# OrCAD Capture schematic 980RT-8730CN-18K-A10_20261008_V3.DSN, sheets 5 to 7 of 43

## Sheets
5 P0011_S1_DUT1: size Custom
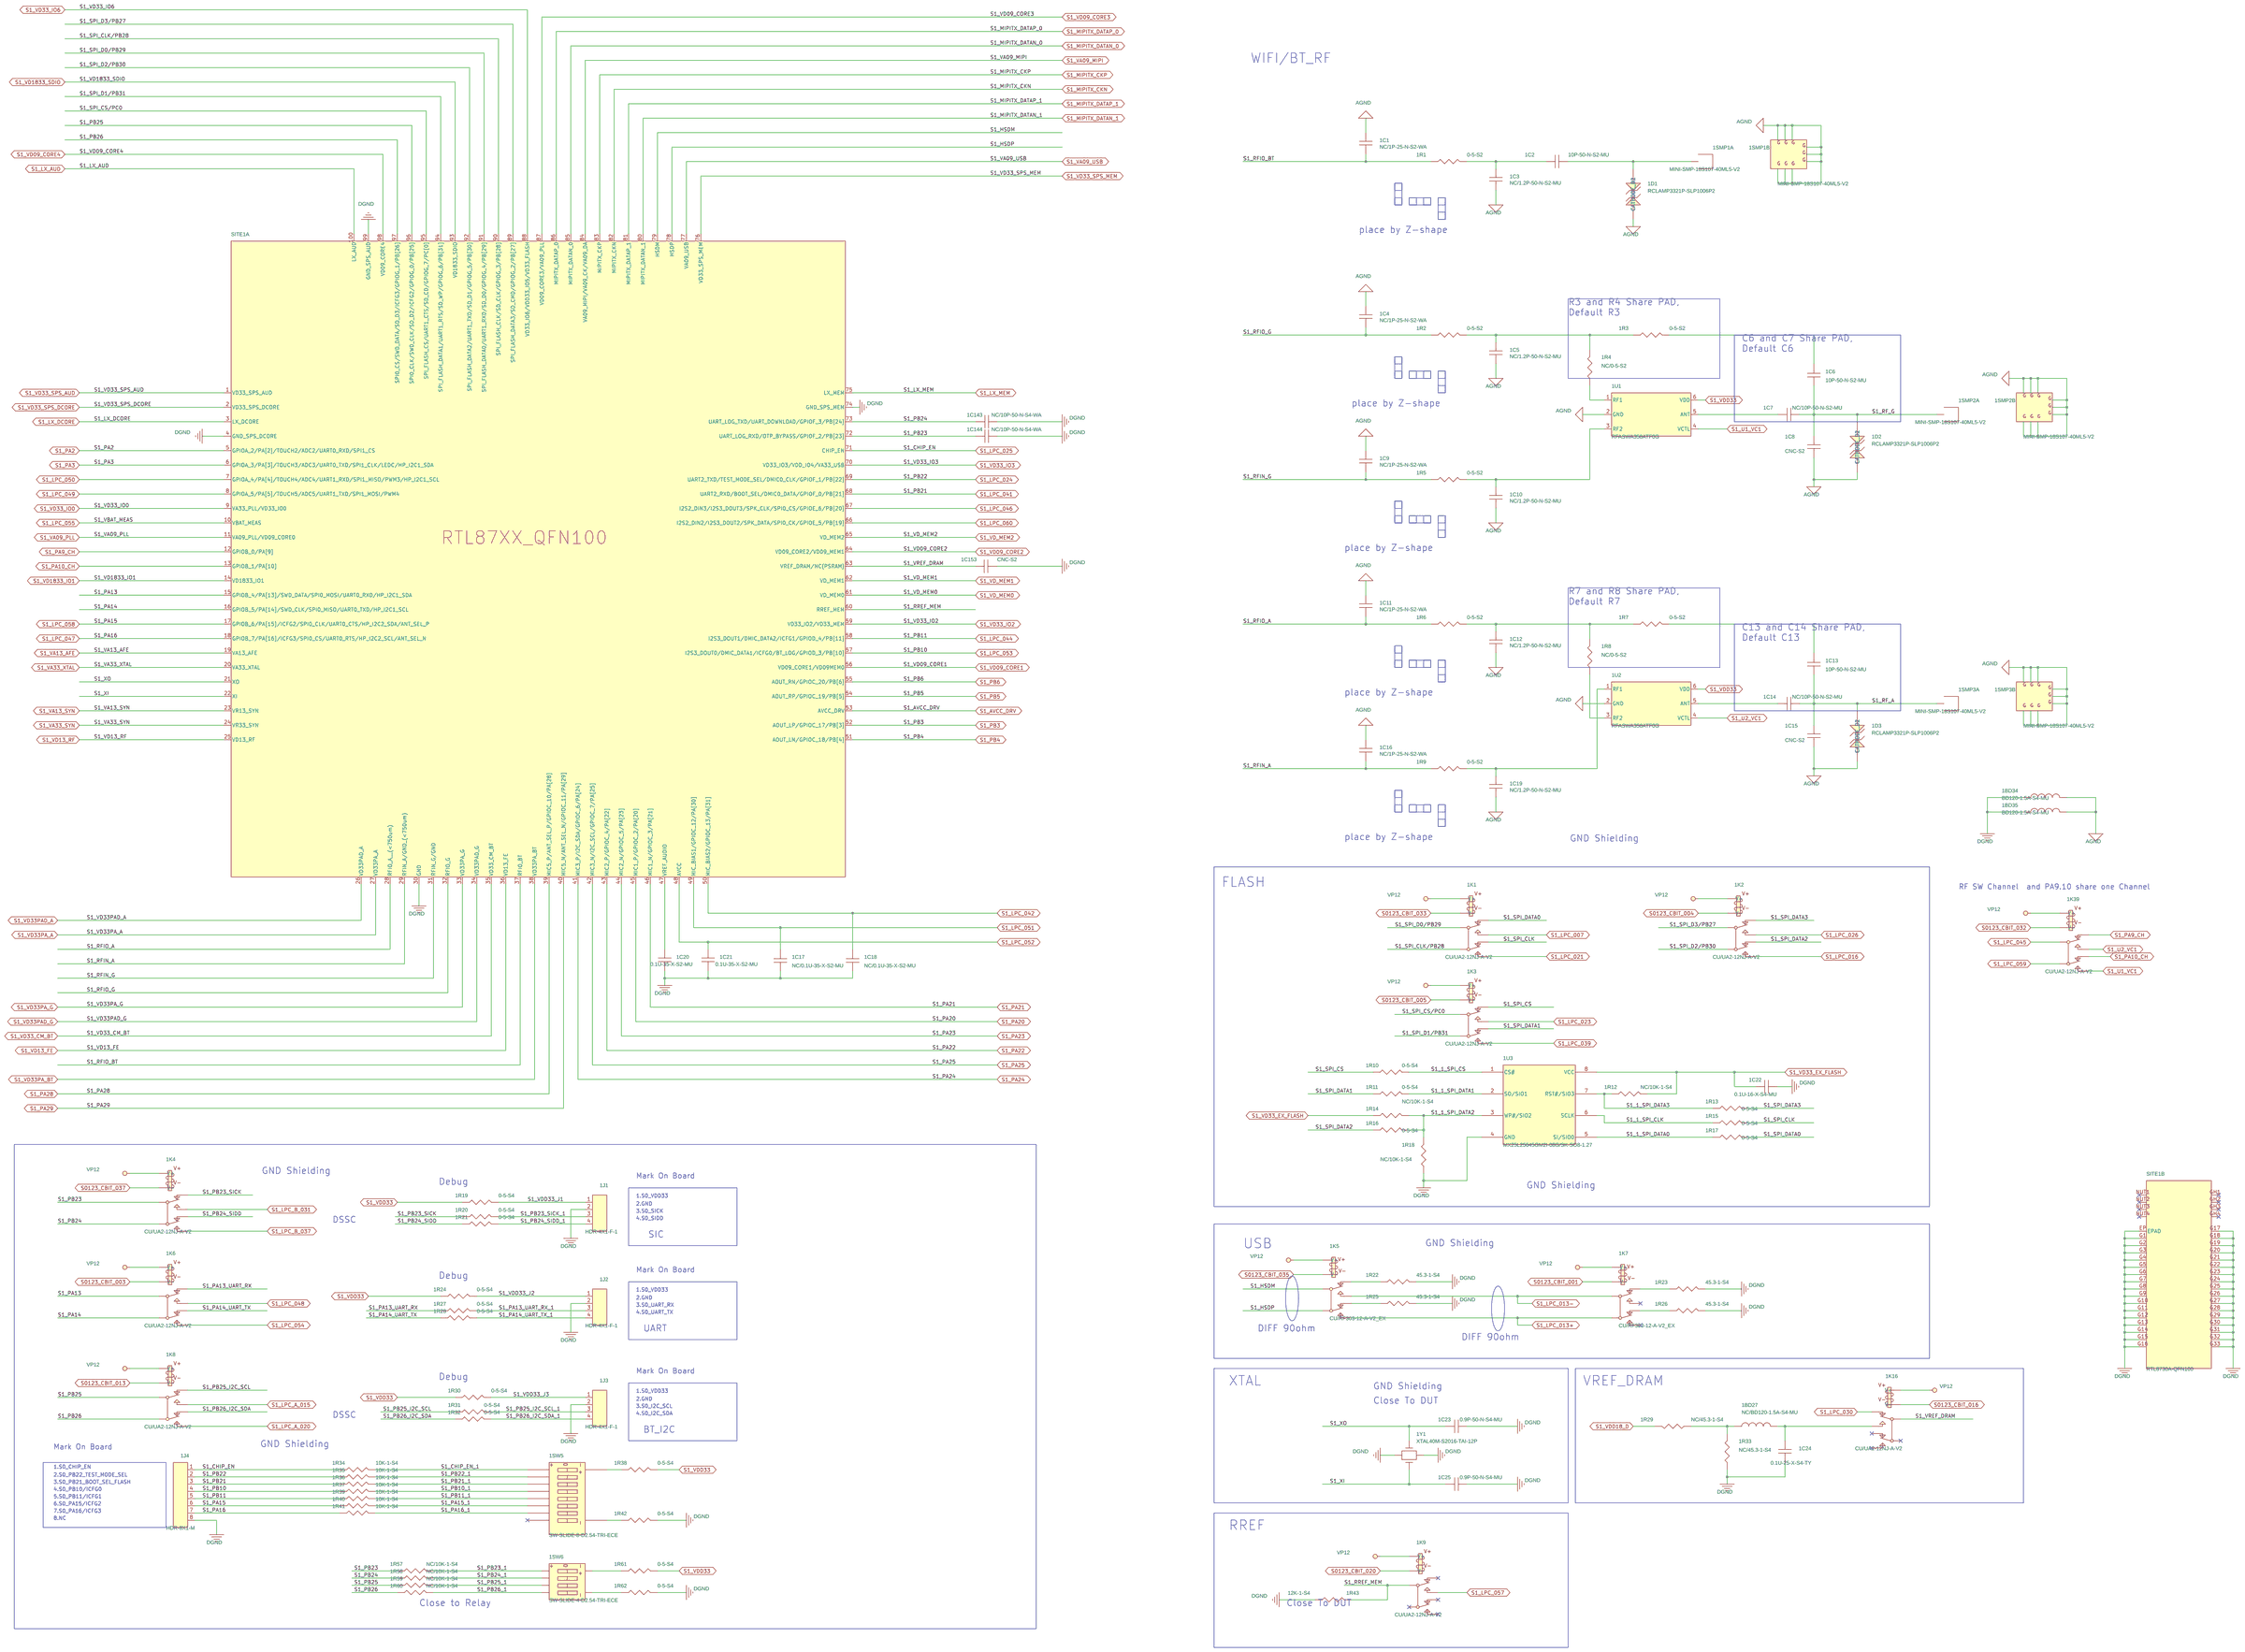
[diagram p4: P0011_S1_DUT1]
6 P0012_S1_Function-test: size A3
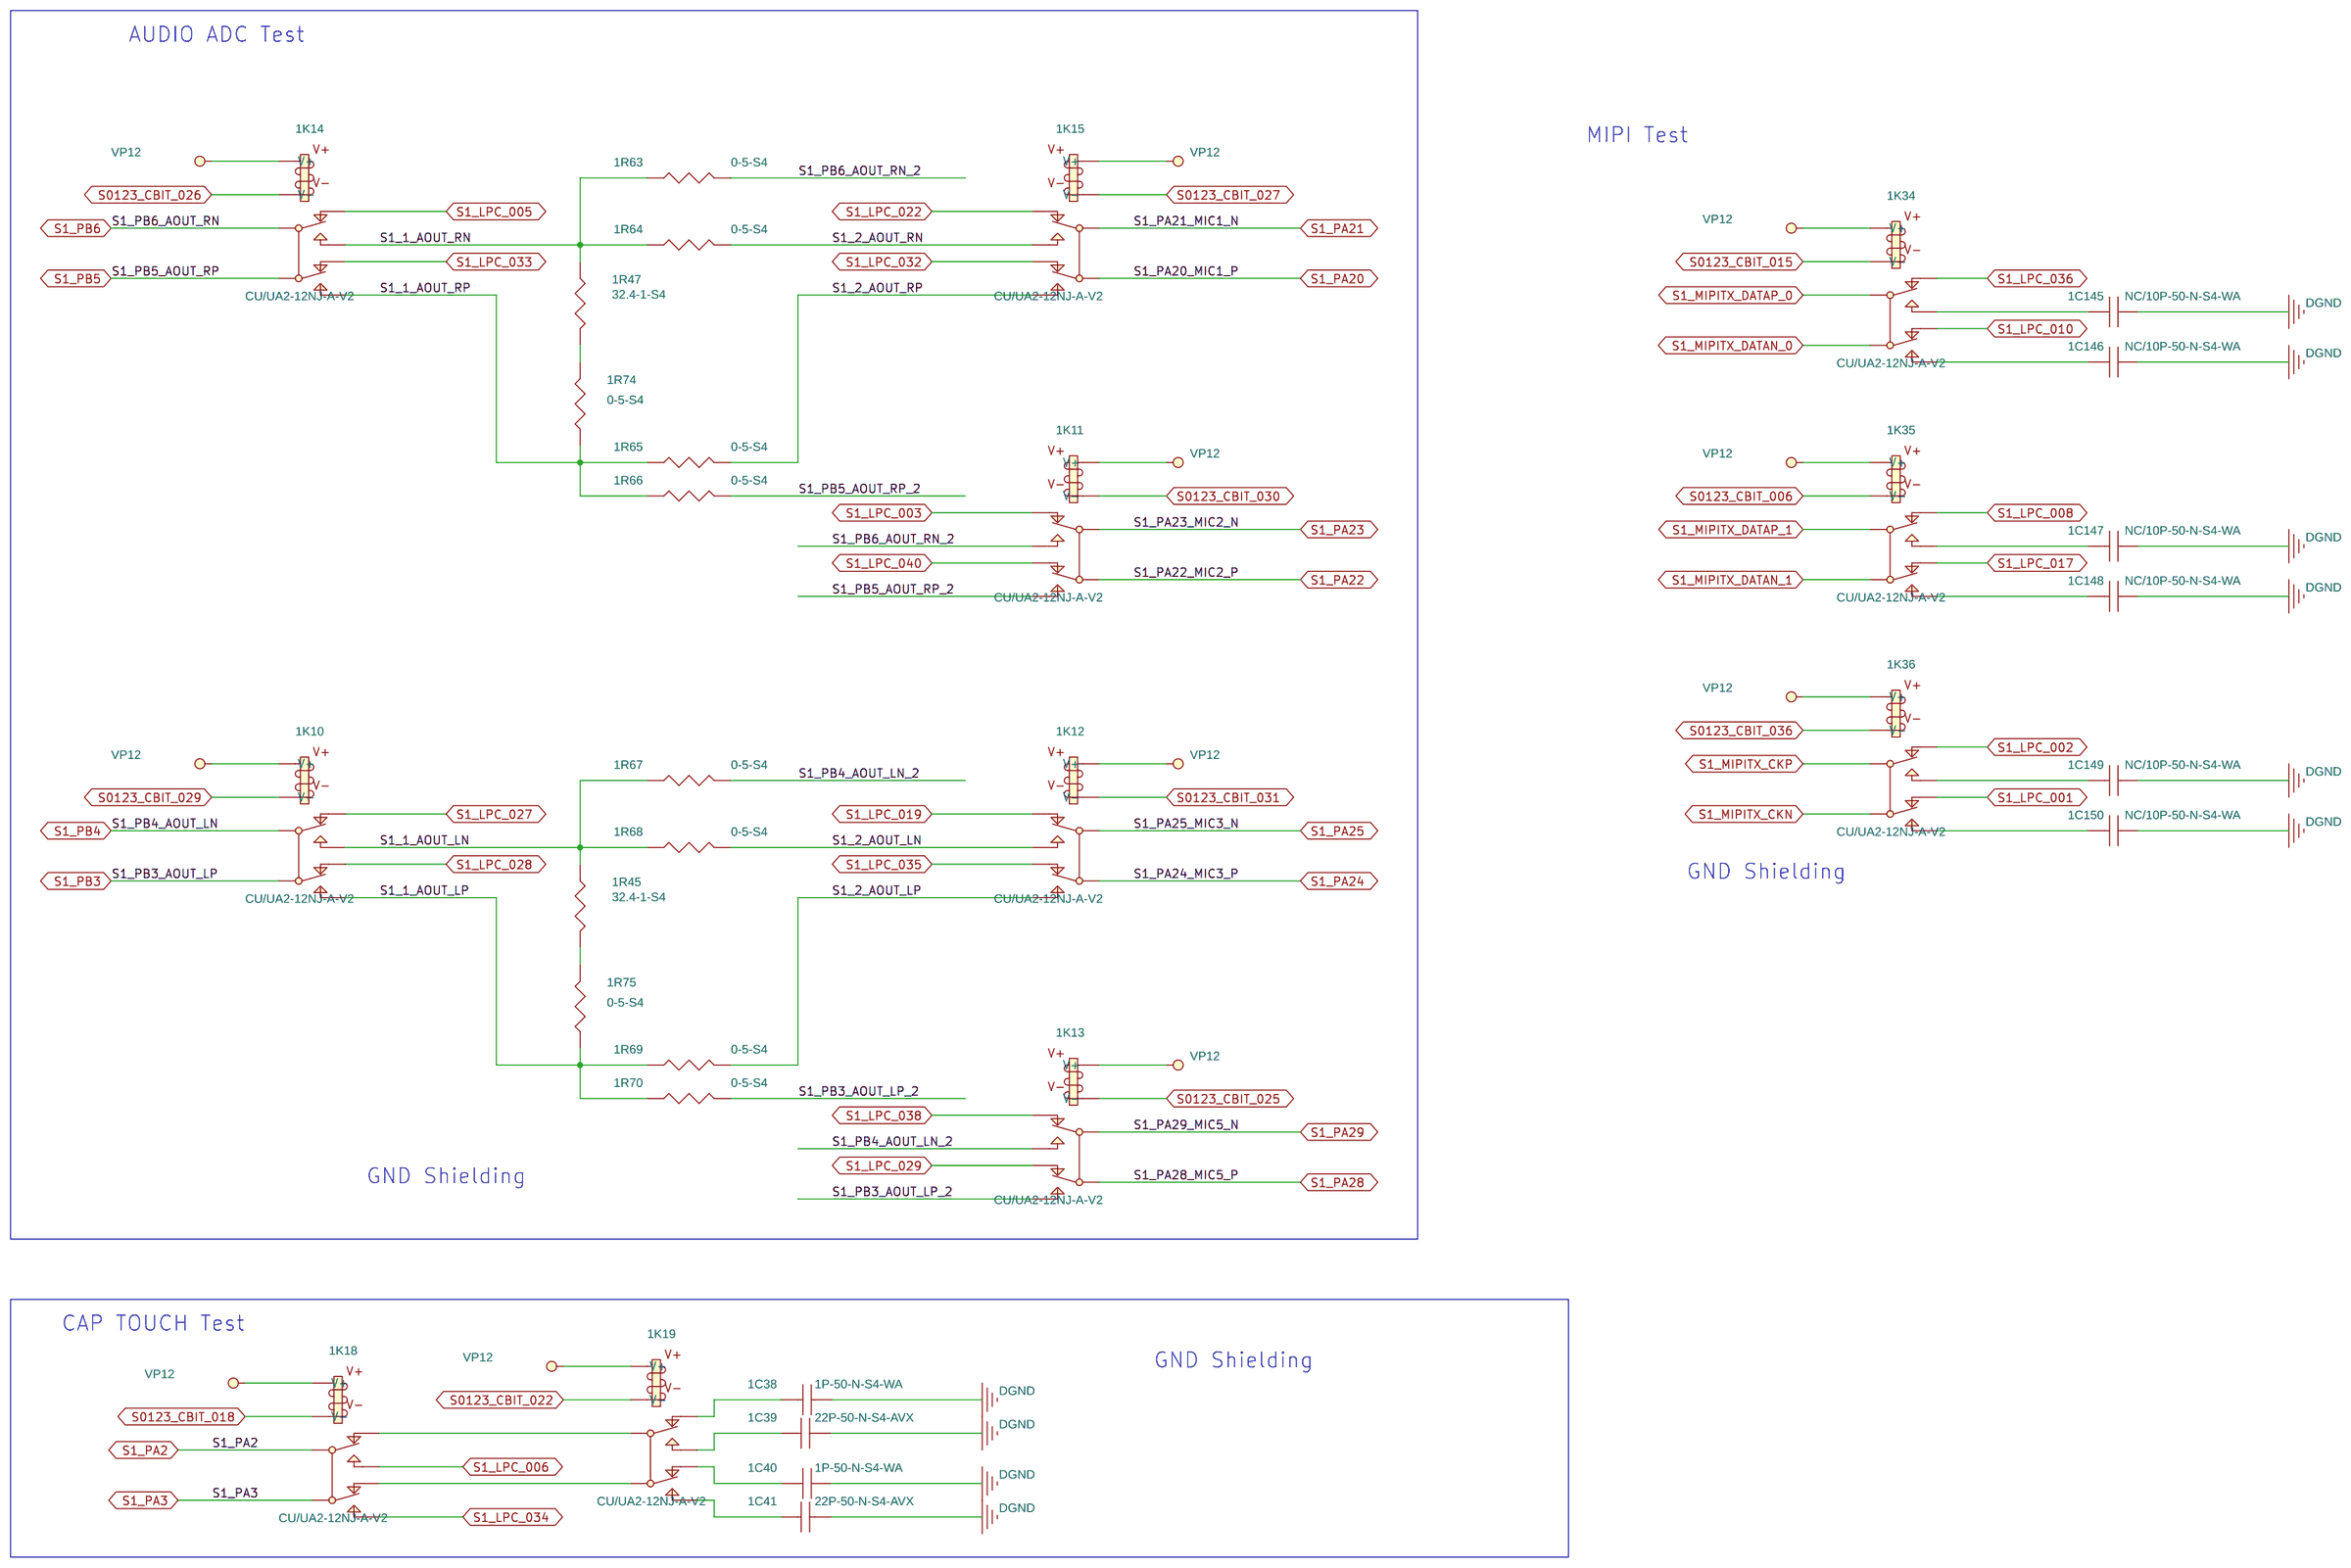
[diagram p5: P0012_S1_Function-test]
7 P0013_S1_Power: size A1
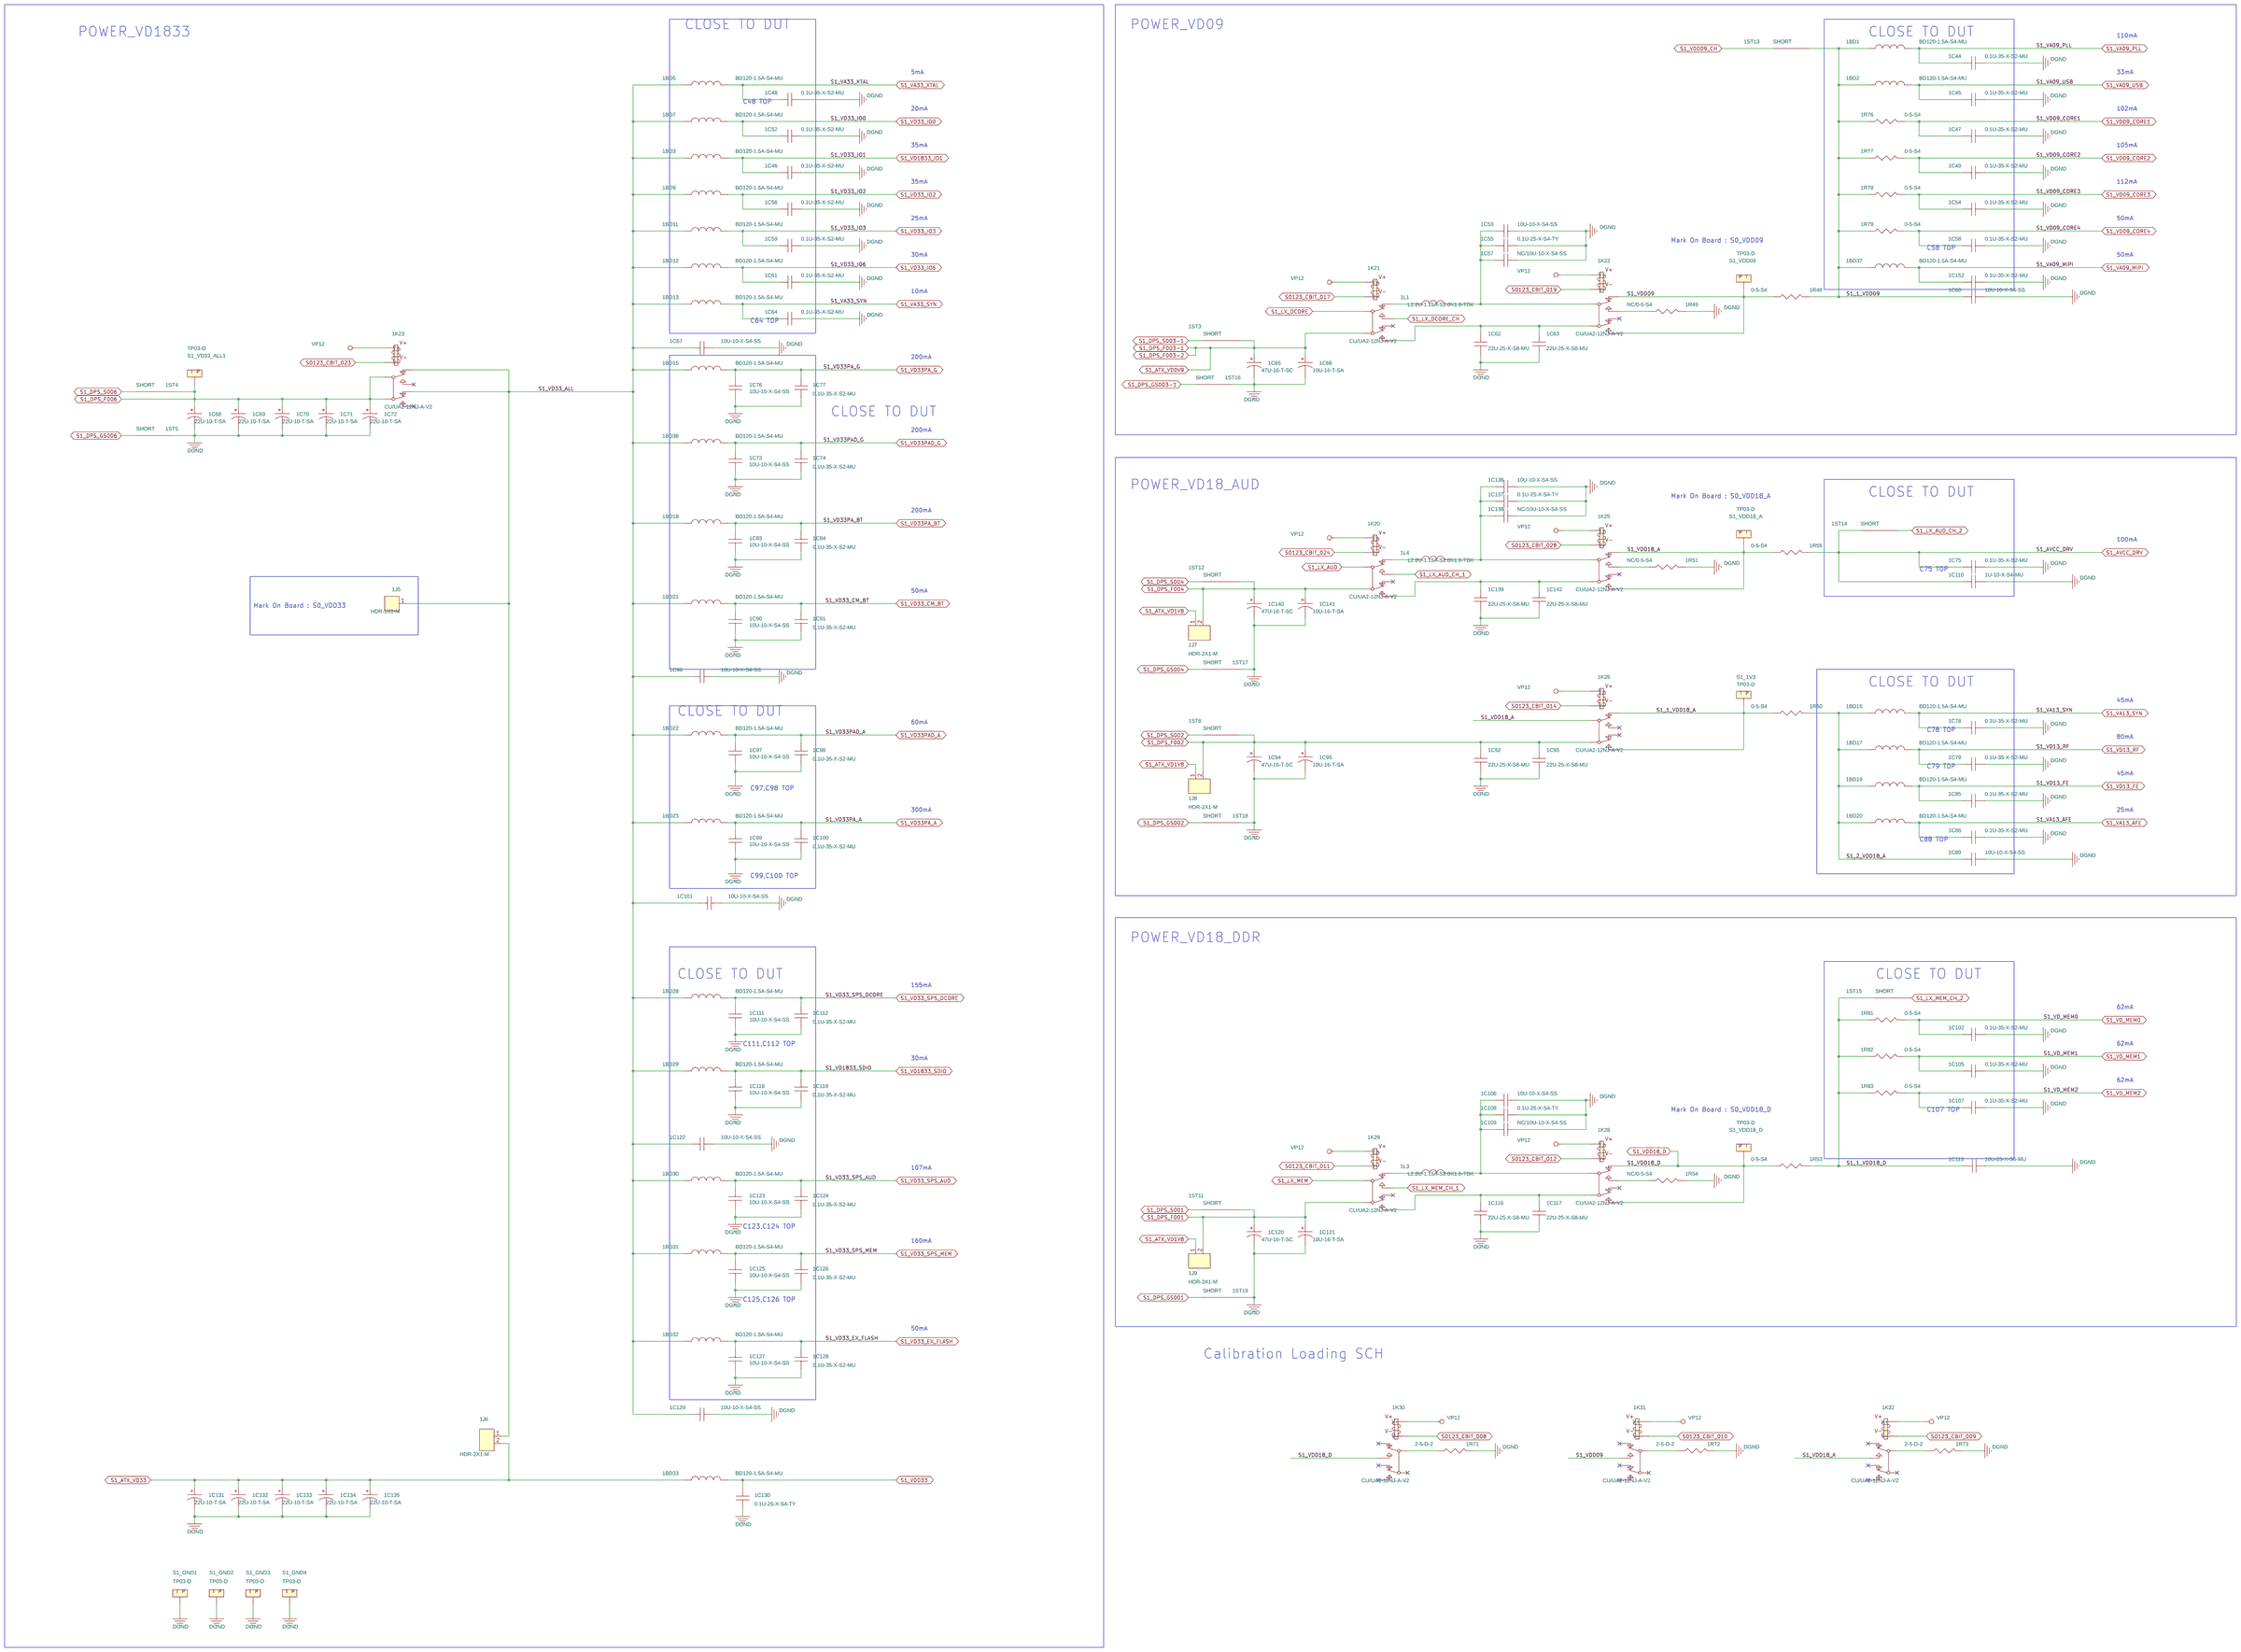
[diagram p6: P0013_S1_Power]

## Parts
sheet P0011_S1_DUT1
1BD27  NC/BD120-1.5A-S4-MU  [FB0402]
1BD34  BD120-1.5A-S4-MU  [FB0402]
1BD35  BD120-1.5A-S4-MU  [FB0402]
1C1  NC/1P-25-N-S2-WA  [C0201]
1C2  10P-50-N-S2-MU  [C0201]
1C3  NC/1.2P-50-N-S2-MU  [C0201]
1C4  NC/1P-25-N-S2-WA  [C0201]
1C5  NC/1.2P-50-N-S2-MU  [C0201]
1C6  10P-50-N-S2-MU  [C0201]
1C7  NC/10P-50-N-S2-MU  [C0201]
1C8  CNC-S2  [C0201]
1C9  NC/1P-25-N-S2-WA  [C0201]
1C10  NC/1.2P-50-N-S2-MU  [C0201]
1C11  NC/1P-25-N-S2-WA  [C0201]
1C12  NC/1.2P-50-N-S2-MU  [C0201]
1C13  10P-50-N-S2-MU  [C0201]
1C14  NC/10P-50-N-S2-MU  [C0201]
1C15  CNC-S2  [C0201]
1C16  NC/1P-25-N-S2-WA  [C0201]
1C17  NC/0.1U-35-X-S2-MU  [C0201]
1C18  NC/0.1U-35-X-S2-MU  [C0201]
1C19  NC/1.2P-50-N-S2-MU  [C0201]
1C20  0.1U-35-X-S2-MU  [C0201]
1C21  0.1U-35-X-S2-MU  [C0201]
1C22  0.1U-16-X-S4-MU  [C0402]
1C23  0.9P-50-N-S4-MU  [C0402]
1C24  0.1U-25-X-S4-TY  [C0402]
1C25  0.9P-50-N-S4-MU  [C0402]
1C143  NC/10P-50-N-S4-WA  [C0402]
1C144  NC/10P-50-N-S4-WA  [C0402]
1C153  CNC-S2  [C0201]
1D1  RCLAMP3321P-SLP1006P2  [DIODE_1X0P6MM]
1D2  RCLAMP3321P-SLP1006P2  [DIODE_1X0P6MM]
1D3  RCLAMP3321P-SLP1006P2  [DIODE_1X0P6MM]
1J1  HDR-4X1-F-1  [CONN_4X1_2P54MM_FL10P5MM]
1J2  HDR-4X1-F-1  [CONN_4X1_2P54MM_FL10P5MM]
1J3  HDR-4X1-F-1  [CONN_4X1_2P54MM_FL10P5MM]
1J4  HDR-8X1-M  [JP_8P_100]
1K1  CU/UA2-12NJ-A-V2  [RL_NECUA2_12V_V2]
1K2  CU/UA2-12NJ-A-V2  [RL_NECUA2_12V_V2]
1K3  CU/UA2-12NJ-A-V2  [RL_NECUA2_12V_V2]
1K4  CU/UA2-12NJ-A-V2  [RL_NECUA2_12V_V2]
1K5  CU/RF303-12-A-V2_EX  [RL_RF303_12V_V2]
1K6  CU/UA2-12NJ-A-V2  [RL_NECUA2_12V_V2]
1K7  CU/RF303-12-A-V2_EX  [RL_RF303_12V_V2]
1K8  CU/UA2-12NJ-A-V2  [RL_NECUA2_12V_V2]
1K9  CU/UA2-12NJ-A-V2  [RL_NECUA2_12V_V2]
1K16  CU/UA2-12NJ-A-V2  [RL_NECUA2_12V_V2]
1K39  CU/UA2-12NJ-A-V2  [RL_NECUA2_12V_V2]
1R1  0-5-S2  [R0201]
1R2  0-5-S2  [R0201]
1R3  0-5-S2  [R0201]
1R4  NC/0-5-S2  [R0201]
1R5  0-5-S2  [R0201]
1R6  0-5-S2  [R0201]
1R7  0-5-S2  [R0201]
1R8  NC/0-5-S2  [R0201]
1R9  0-5-S2  [R0201]
1R10  0-5-S4  [R0402]
1R11  0-5-S4  [R0402]
1R12  NC/10K-1-S4  [R0402]
1R13  0-5-S4  [R0402]
1R14  NC/10K-1-S4  [R0402]
1R15  0-5-S4  [R0402]
1R16  0-5-S4  [R0402]
1R17  0-5-S4  [R0402]
1R18  NC/10K-1-S4  [R0402]
1R19  0-5-S4  [R0402]
1R20  0-5-S4  [R0402]
1R21  0-5-S4  [R0402]
1R22  45.3-1-S4  [R0402]
1R23  45.3-1-S4  [R0402]
1R24  0-5-S4  [R0402]
1R25  45.3-1-S4  [R0402]
1R26  45.3-1-S4  [R0402]
1R27  0-5-S4  [R0402]
1R28  0-5-S4  [R0402]
1R29  NC/45.3-1-S4  [R0402]
1R30  0-5-S4  [R0402]
1R31  0-5-S4  [R0402]
1R32  0-5-S4  [R0402]
1R33  NC/45.3-1-S4  [R0402]
1R34  10K-1-S4  [R0402]
1R35  10K-1-S4  [R0402]
1R36  10K-1-S4  [R0402]
1R37  10K-1-S4  [R0402]
1R38  0-5-S4  [R0402]
1R39  10K-1-S4  [R0402]
1R40  10K-1-S4  [R0402]
1R41  10K-1-S4  [R0402]
1R42  0-5-S4  [R0402]
1R43  12K-1-S4  [R0402]
1R57  NC/10K-1-S4  [R0402]
1R58  NC/10K-1-S4  [R0402]
1R59  NC/10K-1-S4  [R0402]
1R60  NC/10K-1-S4  [R0402]
1R61  0-5-S4  [R0402]
1R62  0-5-S4  [R0402]
1SMP1  MINI-SMP-18S107-40ML5-V2  [CONN_SMP_18S107]  (sections A,B)
1SMP2  MINI-SMP-18S107-40ML5-V2  [CONN_SMP_18S107]  (sections A,B)
1SMP3  MINI-SMP-18S107-40ML5-V2  [CONN_SMP_18S107]  (sections A,B)
1SW5  SW-SLIDE-8-D2.54-TRI-ECE  [SW_DIPX8P_2P54_MM_V2]
1SW6  SW-SLIDE-4-D2.54-TRI-ECE  [SW_DIPX4P_2P54MM_ETD]
1U1  RFASWA358ATF0G  [RF_SW_GW2159_6P]
1U2  RFASWA358ATF0G  [RF_SW_GW2159_6P]
1U3  MX25L25645GM2I-08G/SK-SO8-1.27  [SK_SO8_1P27MM_LOTES]
1Y1  XTAL40M-S2016-TAI-12P  [XTAL_2X1P6MM_4P_0P8MM]
SITE1  RTL8730A-QFN100  [SK_QFN100P_0P35MM_MJC_L8730A]  (sections A,B)
sheet P0012_S1_Function-test
1C38  1P-50-N-S4-WA  [C0402]
1C39  22P-50-N-S4-AVX  [C0402]
1C40  1P-50-N-S4-WA  [C0402]
1C41  22P-50-N-S4-AVX  [C0402]
1C145  NC/10P-50-N-S4-WA  [C0402]
1C146  NC/10P-50-N-S4-WA  [C0402]
1C147  NC/10P-50-N-S4-WA  [C0402]
1C148  NC/10P-50-N-S4-WA  [C0402]
1C149  NC/10P-50-N-S4-WA  [C0402]
1C150  NC/10P-50-N-S4-WA  [C0402]
1K10  CU/UA2-12NJ-A-V2  [RL_NECUA2_12V_V2]
1K11  CU/UA2-12NJ-A-V2  [RL_NECUA2_12V_V2]
1K12  CU/UA2-12NJ-A-V2  [RL_NECUA2_12V_V2]
1K13  CU/UA2-12NJ-A-V2  [RL_NECUA2_12V_V2]
1K14  CU/UA2-12NJ-A-V2  [RL_NECUA2_12V_V2]
1K15  CU/UA2-12NJ-A-V2  [RL_NECUA2_12V_V2]
1K18  CU/UA2-12NJ-A-V2  [RL_NECUA2_12V_V2]
1K19  CU/UA2-12NJ-A-V2  [RL_NECUA2_12V_V2]
1K34  CU/UA2-12NJ-A-V2  [RL_NECUA2_12V_V2]
1K35  CU/UA2-12NJ-A-V2  [RL_NECUA2_12V_V2]
1K36  CU/UA2-12NJ-A-V2  [RL_NECUA2_12V_V2]
1R45  32.4-1-S4  [R0402]
1R47  32.4-1-S4  [R0402]
1R63  0-5-S4  [R0402]
1R64  0-5-S4  [R0402]
1R65  0-5-S4  [R0402]
1R66  0-5-S4  [R0402]
1R67  0-5-S4  [R0402]
1R68  0-5-S4  [R0402]
1R69  0-5-S4  [R0402]
1R70  0-5-S4  [R0402]
1R74  0-5-S4  [R0402]
1R75  0-5-S4  [R0402]
sheet P0013_S1_Power
1BD1  BD120-1.5A-S4-MU  [FB0402]
1BD2  BD120-1.5A-S4-MU  [FB0402]
1BD3  BD120-1.5A-S4-MU  [FB0402]
1BD5  BD120-1.5A-S4-MU  [FB0402]
1BD7  BD120-1.5A-S4-MU  [FB0402]
1BD9  BD120-1.5A-S4-MU  [FB0402]
1BD11  BD120-1.5A-S4-MU  [FB0402]
1BD12  BD120-1.5A-S4-MU  [FB0402]
1BD13  BD120-1.5A-S4-MU  [FB0402]
1BD15  BD120-1.5A-S4-MU  [FB0402]
1BD16  BD120-1.5A-S4-MU  [FB0402]
1BD17  BD120-1.5A-S4-MU  [FB0402]
1BD18  BD120-1.5A-S4-MU  [FB0402]
1BD19  BD120-1.5A-S4-MU  [FB0402]
1BD20  BD120-1.5A-S4-MU  [FB0402]
1BD21  BD120-1.5A-S4-MU  [FB0402]
1BD22  BD120-1.5A-S4-MU  [FB0402]
1BD23  BD120-1.5A-S4-MU  [FB0402]
1BD28  BD120-1.5A-S4-MU  [FB0402]
1BD29  BD120-1.5A-S4-MU  [FB0402]
1BD30  BD120-1.5A-S4-MU  [FB0402]
1BD31  BD120-1.5A-S4-MU  [FB0402]
1BD32  BD120-1.5A-S4-MU  [FB0402]
1BD33  BD120-1.5A-S4-MU  [FB0402]
1BD36  BD120-1.5A-S4-MU  [FB0402]
1BD37  BD120-1.5A-S4-MU  [FB0402]
1C44  0.1U-35-X-S2-MU  [C0201]
1C45  0.1U-35-X-S2-MU  [C0201]
1C46  0.1U-35-X-S2-MU  [C0201]
1C47  0.1U-35-X-S2-MU  [C0201]
1C48  0.1U-35-X-S2-MU  [C0201]
1C49  0.1U-35-X-S2-MU  [C0201]
1C52  0.1U-35-X-S2-MU  [C0201]
1C53  10U-10-X-S4-SS  [C0402]
1C54  0.1U-35-X-S2-MU  [C0201]
1C55  0.1U-25-X-S4-TY  [C0402]
1C56  0.1U-35-X-S2-MU  [C0201]
1C57  NC/10U-10-X-S4-SS  [C0402]
1C58  0.1U-35-X-S2-MU  [C0201]
1C59  0.1U-35-X-S2-MU  [C0201]
1C60  10U-10-X-S4-SS  [C0402]
1C61  0.1U-35-X-S2-MU  [C0201]
1C62  22U-25-X-S8-MU  [C0805]
1C63  22U-25-X-S8-MU  [C0805]
1C64  0.1U-35-X-S2-MU  [C0201]
1C65  47U-16-T-SC  [CODE_C]
1C66  10U-16-T-SA  [CODE_A]
1C67  10U-10-X-S4-SS  [C0402]
1C68  22U-10-T-SA  [CODE_A]
1C69  22U-10-T-SA  [CODE_A]
1C70  22U-10-T-SA  [CODE_A]
1C71  22U-10-T-SA  [CODE_A]
1C72  22U-10-T-SA  [CODE_A]
1C73  10U-10-X-S4-SS  [C0402]
1C74  0.1U-35-X-S2-MU  [C0201]
1C75  0.1U-35-X-S2-MU  [C0201]
1C76  10U-10-X-S4-SS  [C0402]
1C77  0.1U-35-X-S2-MU  [C0201]
1C78  0.1U-35-X-S2-MU  [C0201]
1C79  0.1U-35-X-S2-MU  [C0201]
1C83  10U-10-X-S4-SS  [C0402]
1C84  0.1U-35-X-S2-MU  [C0201]
1C85  0.1U-35-X-S2-MU  [C0201]
1C88  0.1U-35-X-S2-MU  [C0201]
1C89  10U-10-X-S4-SS  [C0402]
1C90  10U-10-X-S4-SS  [C0402]
1C91  0.1U-35-X-S2-MU  [C0201]
1C92  22U-25-X-S8-MU  [C0805]
1C93  22U-25-X-S8-MU  [C0805]
1C94  47U-16-T-SC  [CODE_C]
1C95  10U-16-T-SA  [CODE_A]
1C96  10U-10-X-S4-SS  [C0402]
1C97  10U-10-X-S4-SS  [C0402]
1C98  0.1U-35-X-S2-MU  [C0201]
1C99  10U-10-X-S4-SS  [C0402]
1C100  0.1U-35-X-S2-MU  [C0201]
1C101  10U-10-X-S4-SS  [C0402]
1C102  0.1U-35-X-S2-MU  [C0201]
1C105  0.1U-35-X-S2-MU  [C0201]
1C106  10U-10-X-S4-SS  [C0402]
1C107  0.1U-35-X-S2-MU  [C0201]
1C108  0.1U-25-X-S4-TY  [C0402]
1C109  NC/10U-10-X-S4-SS  [C0402]
1C110  1U-10-X-S4-MU  [C0402]
1C111  10U-10-X-S4-SS  [C0402]
1C112  0.1U-35-X-S2-MU  [C0201]
1C113  10U-25-X-S6-MU  [C0603]
1C116  22U-25-X-S8-MU  [C0805]
1C117  22U-25-X-S8-MU  [C0805]
1C118  10U-10-X-S4-SS  [C0402]
1C119  0.1U-35-X-S2-MU  [C0201]
1C120  47U-16-T-SC  [CODE_C]
1C121  10U-16-T-SA  [CODE_A]
1C122  10U-10-X-S4-SS  [C0402]
1C123  10U-10-X-S4-SS  [C0402]
1C124  0.1U-35-X-S2-MU  [C0201]
1C125  10U-10-X-S4-SS  [C0402]
1C126  0.1U-35-X-S2-MU  [C0201]
1C127  10U-10-X-S4-SS  [C0402]
1C128  0.1U-35-X-S2-MU  [C0201]
1C129  10U-10-X-S4-SS  [C0402]
1C130  0.1U-25-X-S4-TY  [C0402]
1C131  22U-10-T-SA  [CODE_A]
1C132  22U-10-T-SA  [CODE_A]
1C133  22U-10-T-SA  [CODE_A]
1C134  22U-10-T-SA  [CODE_A]
1C135  22U-10-T-SA  [CODE_A]
1C136  10U-10-X-S4-SS  [C0402]
1C137  0.1U-25-X-S4-TY  [C0402]
1C138  NC/10U-10-X-S4-SS  [C0402]
1C139  22U-25-X-S8-MU  [C0805]
1C140  47U-16-T-SC  [CODE_C]
1C141  10U-16-T-SA  [CODE_A]
1C142  22U-25-X-S8-MU  [C0805]
1C152  0.1U-35-X-S2-MU  [C0201]
1J5  HDR-1X1-M  [JP_1P_RD070_040]
1J6  HDR-2X1-M  [JP_2P_100]
1J7  HDR-2X1-M  [JP_2P_100]
1J8  HDR-2X1-M  [JP_2P_100]
1J9  HDR-2X1-M  [JP_2P_100]
1K20  CU/UA2-12NJ-A-V2  [RL_NECUA2_12V_V2]
1K21  CU/UA2-12NJ-A-V2  [RL_NECUA2_12V_V2]
1K22  CU/UA2-12NJ-A-V2  [RL_NECUA2_12V_V2]
1K23  CU/UA2-12NJ-A-V2  [RL_NECUA2_12V_V2]
1K25  CU/UA2-12NJ-A-V2  [RL_NECUA2_12V_V2]
1K26  CU/UA2-12NJ-A-V2  [RL_NECUA2_12V_V2]
1K28  CU/UA2-12NJ-A-V2  [RL_NECUA2_12V_V2]
1K29  CU/UA2-12NJ-A-V2  [RL_NECUA2_12V_V2]
1K30  CU/UA2-12NJ-A-V2  [RL_NECUA2_12V_V2]
1K31  CU/UA2-12NJ-A-V2  [RL_NECUA2_12V_V2]
1K32  CU/UA2-12NJ-A-V2  [RL_NECUA2_12V_V2]
1L1  L2.2U-1.15A-S2.0X1.6-TDK  [IND_VL252012E]
1L3  L2.2U-1.15A-S2.0X1.6-TDK  [IND_VL252012E]
1L4  L2.2U-1.15A-S2.0X1.6-TDK  [IND_VL252012E]
1R48  0-5-S4  [R0402]
1R49  NC/0-5-S4  [R0402]
1R50  0-5-S4  [R0402]
1R51  NC/0-5-S4  [R0402]
1R53  0-5-S4  [R0402]
1R54  NC/0-5-S4  [R0402]
1R55  0-5-S4  [R0402]
1R71  2-5-D-2  [RC02W_27MM]
1R72  2-5-D-2  [RC02W_27MM]
1R73  2-5-D-2  [RC02W_27MM]
1R76  0-5-S4  [R0402]
1R77  0-5-S4  [R0402]
1R78  0-5-S4  [R0402]
1R79  0-5-S4  [R0402]
1R81  0-5-S4  [R0402]
1R82  0-5-S4  [R0402]
1R83  0-5-S4  [R0402]
1ST3  SHORT  [DEFAULT_SHORT_SMALL]
1ST4  SHORT  [DEFAULT_SHORT_SMALL]
1ST5  SHORT  [DEFAULT_SHORT_SMALL]
1ST8  SHORT  [DEFAULT_SHORT_SMALL]
1ST11  SHORT  [DEFAULT_SHORT_SMALL]
1ST12  SHORT  [DEFAULT_SHORT_SMALL]
1ST13  SHORT  [DEFAULT_SHORT_SMALL]
1ST14  SHORT  [DEFAULT_SHORT_SMALL]
1ST15  SHORT  [DEFAULT_SHORT_SMALL]
1ST16  SHORT  [DEFAULT_SHORT_SMALL]
1ST17  SHORT  [DEFAULT_SHORT_SMALL]
1ST18  SHORT  [DEFAULT_SHORT_SMALL]
1ST19  SHORT  [DEFAULT_SHORT_SMALL]
S1_1V3  TP03-D  [TP_060_040]
S1_GND1  TP03-D  [TP_060_040]
S1_GND2  TP03-D  [TP_060_040]
S1_GND3  TP03-D  [TP_060_040]
S1_GND4  TP03-D  [TP_060_040]
S1_VD33_ALL1  TP03-D  [TP_060_040]
S1_VDD09  TP03-D  [TP_060_040]
S1_VDD18_A  TP03-D  [TP_060_040]
S1_VDD18_D  TP03-D  [TP_060_040]

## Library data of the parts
1BD27 = BD120-1.5A-S4-MU: KAIROSNAME: BD27
1BD34 = BD120-1.5A-S4-MU: KAIROSNAME: BD34
1BD35 = BD120-1.5A-S4-MU: KAIROSNAME: BD35
1C1 1C4 1C9 1C11 1C16 = 1P-25-N-S2-WA
1C2 1C6 1C7 1C13 1C14 = 10P-50-N-S2-MU
1C3 1C5 1C10 1C12 1C19 = 1.2P-50-N-S2-MU
1C8 1C15 = CNC-S4
1C17 1C18 1C46 = 0.1U-35-X-S2-MU: KAIROSNAME: C46
1C20 1C21 1C98 = 0.1U-35-X-S2-MU: KAIROSNAME: C98
1C22 = 0.1U-16-X-S4: KAIROSNAME: C22
1C23 = 10P-50-N-S4-MU-1: KAIROSNAME: C23
1C24 = 0.1U-25-X-S4-TY: KAIROSNAME: C24
1C25 = 10P-50-N-S4-MU-1: KAIROSNAME: C25
1C143-1C150 = 10P-50-N-S4-WA
1C48 1C153 = 0.1U-35-X-S2-MU: KAIROSNAME: C48
1D1 = RCLAMP3321P-SLP1006P2: KAIROSNAME: D1
1D2 = RCLAMP3321P-SLP1006P2: KAIROSNAME: D2
1D3 = RCLAMP3321P-SLP1006P2: KAIROSNAME: D3
1J1-1J3 = HDR-4X1-F-1
1J4 = HDR-8X1-M: KAIROSNAME: J4
1K1 1K39 = CU_UA2-12NJ-A-V2: KAIROSNAME: K1
1K2 1K16 = CU_UA2-12NJ-A-V2: KAIROSNAME: K2
1K3 = CU_UA2-12NJ-A-V2: KAIROSNAME: K3
1K4 = CU_UA2-12NJ-A-V2: KAIROSNAME: K4
1K5 = CU_RF303-12-A-V2_EX: KAIROSNAME: K5
1K6 = CU_UA2-12NJ-A-V2: KAIROSNAME: K6
1K7 = CU_RF303-12-A-V2_EX: KAIROSNAME: K7
1K8 = CU_UA2-12NJ-A-V2: KAIROSNAME: K8
1K9 = CU_UA2-12NJ-A-V2: KAIROSNAME: K9
1R1-1R9 = 0-5-S2
1R10 = 0-5-S4: KAIROSNAME: R10
1R11 = 0-5-S4: KAIROSNAME: R11
1R12 = 10K-1-S4: KAIROSNAME: R12
1R13 = 0-5-S4: KAIROSNAME: R13
1R14 = 10K-1-S4: KAIROSNAME: R14
1R15 = 0-5-S4: KAIROSNAME: R15
1R16 = 0-5-S4: KAIROSNAME: R16
1R17 = 0-5-S4: KAIROSNAME: R17
1R18 = 10K-1-S4: KAIROSNAME: R18
1R19 = 0-5-S4: KAIROSNAME: R19
1R20 = 0-5-S4: KAIROSNAME: R20
1R21 = 0-5-S4: KAIROSNAME: R21
1R22 = 45.3-1-S4: KAIROSNAME: R22
1R23 = 45.3-1-S4: KAIROSNAME: R23
1R24 = 0-5-S4: KAIROSNAME: R24
1R25 = 45.3-1-S4: KAIROSNAME: R25
1R26 = 45.3-1-S4: KAIROSNAME: R26
1R27 = 0-5-S4: KAIROSNAME: R27
1R28 = 0-5-S4: KAIROSNAME: R28
1R29 = 45.3-1-S4: KAIROSNAME: R29
1R30 = 0-5-S4: KAIROSNAME: R30
1R31 = 0-5-S4: KAIROSNAME: R31
1R32 = 0-5-S4: KAIROSNAME: R32
1R33 = 45.3-1-S4: KAIROSNAME: R33
1R34 = 10K-1-S4: KAIROSNAME: R34
1R35 = 10K-1-S4: KAIROSNAME: R35
1R36 = 10K-1-S4: KAIROSNAME: R36
1R37 = 10K-1-S4: KAIROSNAME: R37
1R38 = 0-5-S4: KAIROSNAME: R38
1R39 = 10K-1-S4: KAIROSNAME: R39
1R40 = 10K-1-S4: KAIROSNAME: R40
1R41 = 10K-1-S4: KAIROSNAME: R41
1R42 = 0-5-S4: KAIROSNAME: R42
1R43 = 12K-1-S4: KAIROSNAME: R43
1R57 = 10K-1-S4: KAIROSNAME: R57
1R58 = 10K-1-S4: KAIROSNAME: R58
1R59 = 10K-1-S4: KAIROSNAME: R59
1R60 = 10K-1-S4: KAIROSNAME: R60
1R61 = 0-5-S4: KAIROSNAME: R61
1R62 = 0-5-S4: KAIROSNAME: R62
1SMP1 = MINI-SMP-18S107-40ML5-V2: KAIROSNAME: SMP1A
1SMP2 = MINI-SMP-18S107-40ML5-V2: KAIROSNAME: SMP2A
1SMP3 = MINI-SMP-18S107-40ML5-V2: KAIROSNAME: SMP3A
1SW5 = SW-SLIDE-8-D2.54-TRI-ECE
1SW6 = SW-SLIDE-4-D2.54-TRI-ECE
1U1 1U2 = RFASWA358ATF0G
1U3 = MX25R6435FM2IL0-SOP8: KAIROSNAME: U3
1Y1 = XTAL40M-S2016-TAI-12P: KAIROSNAME: Y1
SITE1 = RTL8730A-QFN100
1C38 = 10P-50-N-S4-MU-1: KAIROSNAME: C38
1C39 = 33P-50-N-S4-WA: KAIROSNAME: C39
1C40 = 10P-50-N-S4-MU-1: KAIROSNAME: C40
1C41 = 33P-50-N-S4-WA: KAIROSNAME: C41
1K10 = CU_UA2-12NJ-A-V2: KAIROSNAME: K10
1K11 = CU_UA2-12NJ-A-V2: KAIROSNAME: K11
1K12 = CU_UA2-12NJ-A-V2: KAIROSNAME: K12
1K13 = CU_UA2-12NJ-A-V2: KAIROSNAME: K13
1K14 = CU_UA2-12NJ-A-V2: KAIROSNAME: K14
1K15 1K34-1K36 = CU_UA2-12NJ-A-V2: KAIROSNAME: K15
1K18 = CU_UA2-12NJ-A-V2: KAIROSNAME: K18
1K19 = CU_UA2-12NJ-A-V2: KAIROSNAME: K19
1R45 = 32.4-1-S4: KAIROSNAME: R45
1R47 = 32.4-1-S4: KAIROSNAME: R47
1R63 = 0-5-S4: KAIROSNAME: R63
1R64 = 0-5-S4: KAIROSNAME: R64
1R65 1R74 1R75 = 0-5-S4: KAIROSNAME: R65
1R66 = 0-5-S4: KAIROSNAME: R66
1R67 = 0-5-S4: KAIROSNAME: R67
1R68 = 0-5-S4: KAIROSNAME: R68
1R69 = 0-5-S4: KAIROSNAME: R69
1R70 = 0-5-S4: KAIROSNAME: R70
1BD1 = BD120-1.5A-S4-MU: KAIROSNAME: BD1
1BD2 = BD120-1.5A-S4-MU: KAIROSNAME: BD2
1BD3 = BD120-1.5A-S4-MU: KAIROSNAME: BD3
1BD5 = BD120-1.5A-S4-MU: KAIROSNAME: BD5
1BD7 = BD120-1.5A-S4-MU: KAIROSNAME: BD7
1BD9 = BD120-1.5A-S4-MU: KAIROSNAME: BD9
1BD11 = BD120-1.5A-S4-MU: KAIROSNAME: BD11
1BD12 = BD120-1.5A-S4-MU: KAIROSNAME: BD12
1BD13 = BD120-1.5A-S4-MU: KAIROSNAME: BD13
1BD15 1BD36 = BD120-1.5A-S4-MU: KAIROSNAME: BD15
1BD16 = BD120-1.5A-S4-MU: KAIROSNAME: BD16
1BD17 = BD120-1.5A-S4-MU: KAIROSNAME: BD17
1BD18 = BD120-1.5A-S4-MU: KAIROSNAME: BD18
1BD19 = BD120-1.5A-S4-MU: KAIROSNAME: BD19
1BD20 = BD120-1.5A-S4-MU: KAIROSNAME: BD20
1BD21 = BD120-1.5A-S4-MU: KAIROSNAME: BD21
1BD22 = BD120-1.5A-S4-MU: KAIROSNAME: BD22
1BD23 = BD120-1.5A-S4-MU: KAIROSNAME: BD23
1BD28 = BD120-1.5A-S4-MU: KAIROSNAME: BD28
1BD29 = BD120-1.5A-S4-MU: KAIROSNAME: BD29
1BD30 = BD120-1.5A-S4-MU: KAIROSNAME: BD30
1BD31 = BD120-1.5A-S4-MU: KAIROSNAME: BD31
1BD32 = BD120-1.5A-S4-MU: KAIROSNAME: BD32
1BD33 = BD120-1.5A-S4-MU: KAIROSNAME: BD33
1BD37 = BD120-1.5A-S4-MU: KAIROSNAME: BD10
1C44 = 0.1U-35-X-S2-MU: KAIROSNAME: C44
1C45 = 0.1U-35-X-S2-MU: KAIROSNAME: C45
1C47 = 0.1U-35-X-S2-MU: KAIROSNAME: C47
1C49 = 0.1U-35-X-S2-MU: KAIROSNAME: C49
1C52 = 0.1U-35-X-S2-MU: KAIROSNAME: C52
1C53 = 10U-10-X-S4-SS: KAIROSNAME: C53
1C54 = 0.1U-35-X-S2-MU: KAIROSNAME: C54
1C55 = 0.1U-25-X-S4-TY: KAIROSNAME: C55
1C56 = 0.1U-35-X-S2-MU: KAIROSNAME: C56
1C57 = 10U-10-X-S4-SS: KAIROSNAME: C57
1C58 1C152 = 0.1U-35-X-S2-MU: KAIROSNAME: C58
1C59 = 0.1U-35-X-S2-MU: KAIROSNAME: C59
1C60 = 10U-10-X-S4-SS: KAIROSNAME: C60
1C61 = 0.1U-35-X-S2-MU: KAIROSNAME: C61
1C62 = 22U-25-X-S8-MU: KAIROSNAME: C62
1C63 = 22U-25-X-S8-MU: KAIROSNAME: C63
1C64 = 0.1U-35-X-S2-MU: KAIROSNAME: C64
1C65 = 47U-16-T-SC: KAIROSNAME: C65
1C66 = 10U-16-T-SA: KAIROSNAME: C66
1C67 = 10U-10-X-S4-SS: KAIROSNAME: C67
1C68 = 22U-10-T-SA: KAIROSNAME: C68
1C69 = 22U-10-T-SA: KAIROSNAME: C69
1C70 = 22U-10-T-SA: KAIROSNAME: C70
1C71 = 22U-10-T-SA: KAIROSNAME: C71
1C72 = 22U-10-T-SA: KAIROSNAME: C72
1C73 1C76 = 10U-10-X-S4-SS: KAIROSNAME: C76
1C74 1C77 = 0.1U-35-X-S2-MU: KAIROSNAME: C77
1C75 = 0.1U-35-X-S2-MU: KAIROSNAME: C75
1C78 = 0.1U-35-X-S2-MU: KAIROSNAME: C78
1C79 = 0.1U-35-X-S2-MU: KAIROSNAME: C79
1C83 = 10U-10-X-S4-SS: KAIROSNAME: C83
1C84 = 0.1U-35-X-S2-MU: KAIROSNAME: C84
1C85 = 0.1U-35-X-S2-MU: KAIROSNAME: C85
1C88 = 0.1U-35-X-S2-MU: KAIROSNAME: C88
1C89 = 10U-10-X-S4-SS: KAIROSNAME: C89
1C90 = 10U-10-X-S4-SS: KAIROSNAME: C90
1C91 = 0.1U-35-X-S2-MU: KAIROSNAME: C91
1C92 = 22U-25-X-S8-MU: KAIROSNAME: C92
1C93 = 22U-25-X-S8-MU: KAIROSNAME: C93
1C94 = 47U-16-T-SC: KAIROSNAME: C94
1C95 = 10U-16-T-SA: KAIROSNAME: C95
1C96 = 10U-10-X-S4-SS: KAIROSNAME: C96
1C97 = 10U-10-X-S4-SS: KAIROSNAME: C97
1C99 = 10U-10-X-S4-SS: KAIROSNAME: C99
1C100 = 0.1U-35-X-S2-MU: KAIROSNAME: C100
1C101 = 10U-10-X-S4-SS: KAIROSNAME: C101
1C102 = 0.1U-35-X-S2-MU: KAIROSNAME: C102
1C105 = 0.1U-35-X-S2-MU: KAIROSNAME: C105
1C106 = 10U-10-X-S4-SS: KAIROSNAME: C106
1C107 = 0.1U-35-X-S2-MU: KAIROSNAME: C107
1C108 = 0.1U-25-X-S4-TY: KAIROSNAME: C108
1C109 = 10U-10-X-S4-SS: KAIROSNAME: C109
1C110 = 10U-10-X-S4-SS: KAIROSNAME: C110
1C111 = 10U-10-X-S4-SS: KAIROSNAME: C111
1C112 = 0.1U-35-X-S2-MU: KAIROSNAME: C112
1C113 = 10U-25-X-S6-MU: KAIROSNAME: C113
1C116 = 22U-25-X-S8-MU: KAIROSNAME: C116
1C117 = 22U-25-X-S8-MU: KAIROSNAME: C117
1C118 = 10U-10-X-S4-SS: KAIROSNAME: C118
1C119 = 0.1U-35-X-S2-MU: KAIROSNAME: C119
1C120 = 47U-16-T-SC: KAIROSNAME: C120
1C121 = 10U-16-T-SA: KAIROSNAME: C121
1C122 = 10U-10-X-S4-SS: KAIROSNAME: C122
1C123 = 10U-10-X-S4-SS: KAIROSNAME: C123
1C124 = 0.1U-35-X-S2-MU: KAIROSNAME: C124
1C125 = 10U-10-X-S4-SS: KAIROSNAME: C125
1C126 = 0.1U-35-X-S2-MU: KAIROSNAME: C126
1C127 = 10U-10-X-S4-SS: KAIROSNAME: C127
1C128 = 0.1U-35-X-S2-MU: KAIROSNAME: C128
1C129 = 10U-10-X-S4-SS: KAIROSNAME: C129
1C130 = 0.1U-25-X-S4-TY: KAIROSNAME: C130
1C131 = 22U-10-T-SA: KAIROSNAME: C131
1C132 = 22U-10-T-SA: KAIROSNAME: C132
1C133 = 22U-10-T-SA: KAIROSNAME: C133
1C134 = 22U-10-T-SA: KAIROSNAME: C134
1C135 = 22U-10-T-SA: KAIROSNAME: C135
1C136 = 10U-10-X-S4-SS: KAIROSNAME: C136
1C137 = 0.1U-25-X-S4-TY: KAIROSNAME: C137
1C138 = 10U-10-X-S4-SS: KAIROSNAME: C138
1C139 = 22U-25-X-S8-MU: KAIROSNAME: C139
1C140 = 47U-16-T-SC: KAIROSNAME: C140
1C141 = 10U-16-T-SA: KAIROSNAME: C141
1C142 = 22U-25-X-S8-MU: KAIROSNAME: C142
1J5 = HDR-1X1-M: KAIROSNAME: J5
1J6 = HDR-2X1-M: KAIROSNAME: J6
1J7 = HDR-2X1-M: KAIROSNAME: J7
1J8 = HDR-2X1-M: KAIROSNAME: J8
1J9 = HDR-2X1-M: KAIROSNAME: J9
1K20 = CU_UA2-12NJ-A-V2: KAIROSNAME: K20
1K21 = CU_UA2-12NJ-A-V2: KAIROSNAME: K21
1K22 = CU_UA2-12NJ-A-V2: KAIROSNAME: K22
1K23 = CU_UA2-12NJ-A-V2: KAIROSNAME: K23
1K25 = CU_UA2-12NJ-A-V2: KAIROSNAME: K25
1K26 = CU_UA2-12NJ-A-V2: KAIROSNAME: K26
1K28 1K30-1K32 = CU_UA2-12NJ-A-V2: KAIROSNAME: K28
1K29 = CU_UA2-12NJ-A-V2: KAIROSNAME: K29
1L1 = L2.2U-1.15A-S2.0X1.6-TDK: KAIROSNAME: L1
1L3 = L2.2U-1.15A-S2.0X1.6-TDK: KAIROSNAME: L3
1L4 = L2.2U-1.15A-S2.0X1.6-TDK: KAIROSNAME: L4
1R48 = 0-5-S4: KAIROSNAME: R48
1R49 = 0-5-S4: KAIROSNAME: R49
1R50 = 0-5-S4: KAIROSNAME: R50
1R51 = 0-5-S4: KAIROSNAME: R51
1R53 = 0-5-S4: KAIROSNAME: R53
1R54 = 0-5-S4: KAIROSNAME: R54
1R55 = 0-5-S4: KAIROSNAME: R55
1R71-1R73 = 2-5-D-2
1R76-1R79 1R81-1R83 = 0-5-S4
1ST3 1ST13-1ST15 = SHORT: KAIROSNAME: ST3
1ST4 = SHORT: KAIROSNAME: ST4
1ST5 1ST16-1ST19 = SHORT: KAIROSNAME: ST5
1ST8 = SHORT: KAIROSNAME: ST8
1ST11 = SHORT: KAIROSNAME: ST11
1ST12 = SHORT: KAIROSNAME: ST12
S1_1V3 = TP03-D: KAIROSNAME: S0_TP_VD3
S1_GND1 = TP03-D: KAIROSNAME: S0_GND1
S1_GND2 = TP03-D: KAIROSNAME: S0_GND2
S1_GND3 = TP03-D: KAIROSNAME: S0_GND3
S1_GND4 = TP03-D: KAIROSNAME: S0_GND4
S1_VD33_ALL1 = TP03-D: KAIROSNAME: S0_VD33_ALL1
S1_VDD09 = TP03-D: KAIROSNAME: S0_VDD09
S1_VDD18_A = TP03-D: KAIROSNAME: S0_VDD18_A
S1_VDD18_D = TP03-D: KAIROSNAME: S0_VDD18_D

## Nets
AGND: 1BD34.2 1BD35.2 1C1.1 1C3.2 1C4.1 1C5.2 1C8.2 1C9.1 1C10.2 1C11.1 1C12.2 1C15.2 1C16.1 1C19.2 1D1.2(CATHODE_D2) 1D2.2(CATHODE_D2) 1D3.2(CATHODE_D2) 1SMP1.G1 1SMP1.G2 1SMP1.G3 1SMP1.G4 1SMP1.G5 1SMP1.G6 1SMP1.G7 1SMP1.G8 1SMP1.G9 1SMP2.G1 1SMP2.G2 1SMP2.G3 1SMP2.G4 1SMP2.G5 1SMP2.G6 1SMP2.G7 1SMP2.G8 1SMP2.G9 1SMP3.G1 1SMP3.G2 1SMP3.G3 1SMP3.G4 1SMP3.G5 1SMP3.G6 1SMP3.G7 1SMP3.G8 1SMP3.G9 1U1.2(GND) 1U2.2(GND) ; also on sheet 2 8 11 14 17 20 23
DGND: 1BD34.1 1BD35.1 1C17.1 1C18.1 1C20.2 1C21.2 1C22.2 1C23.1 1C24.2 1C25.1 1C38.1 1C39.2 1C40.1 1C41.2 1C44.2 1C45.2 1C46.2 1C47.2 1C48.2 1C49.2 1C52.2 1C53.2 1C54.2 1C55.2 1C56.2 1C57.2 1C58.2 1C59.2 1C60.2 1C61.2 1C62.2 1C63.2 1C64.2 1C65.2 1C66.2 1C67.2 1C68.2 1C69.2 1C70.2 1C71.2 1C72.2 1C73.2 1C74.2 1C75.2 1C76.2 1C77.2 1C78.2 1C79.2 1C83.2 1C84.2 1C85.2 1C88.2 1C89.2 1C90.2 1C91.2 1C92.2 1C93.2 1C94.2 1C95.2 1C96.2 1C97.2 1C98.2 1C99.2 1C100.2 1C101.2 1C102.2 1C105.2 1C106.2 1C107.2 1C108.2 1C109.2 1C110.2 1C111.2 1C112.2 1C113.1 1C116.2 1C117.2 1C118.2 1C119.2 1C120.2 1C121.2 1C122.2 1C123.2 1C124.2 1C125.2 1C126.2 1C127.2 1C128.2 1C129.2 1C130.2 1C131.2 1C132.2 1C133.2 1C134.2 1C135.2 1C136.2 1C137.2 1C138.2 1C139.2 1C140.2 1C141.2 1C142.2 1C143.1 1C144.1 1C145.1 1C146.1 1C147.1 1C148.1 1C149.1 1C150.1 1C152.2 1C153.2 1J1.2 1J2.2 1J3.2 1J4.8 1R18.1 1R22.2 1R23.2 1R25.2 1R26.2 1R33.1 1R42.2 1R43.2 1R49.2 1R51.2 1R54.2 1R62.2 1R71.2 1R72.2 1R73.2 1ST5.2 1ST16.2 1ST17.2 1ST18.2 1ST19.2 1U3.4(GND) 1Y1.2 1Y1.4 S1_GND1.1(TP) S1_GND2.1(TP) S1_GND3.1(TP) S1_GND4.1(TP) SITE1.4(GND_SPS_DCORE) SITE1.30(GND) SITE1.74(GND_SPS_MEM) SITE1.99(GND_SPS_AUD) SITE1.EP(EPAD) SITE1.G1 SITE1.G2 SITE1.G3 SITE1.G4 SITE1.G5 SITE1.G6 SITE1.G7 SITE1.G8 SITE1.G9 SITE1.G10 SITE1.G11 SITE1.G12 SITE1.G13 SITE1.G14 SITE1.G15 SITE1.G16 SITE1.G17 SITE1.G18 SITE1.G19 SITE1.G20 SITE1.G21 SITE1.G22 SITE1.G23 SITE1.G24 SITE1.G25 SITE1.G26 SITE1.G27 SITE1.G28 SITE1.G29 SITE1.G30 SITE1.G31 SITE1.G32 SITE1.G33 ; also on sheet 2 3 4 8 9 10 11 12 13 14 15 16 17 18 19 20 21 22 23 24 25 26 27 29 30 32 34 37 39
S1_1_AOUT_LN: 1K10.4 1R45.1 1R67.1 1R68.1
S1_1_AOUT_LP: 1K10.5 1R69.1 1R70.1 1R75.1
S1_1_AOUT_RN: 1K14.4 1R47.1 1R63.1 1R64.1
S1_1_AOUT_RP: 1K14.5 1R65.1 1R66.1 1R74.1
S1_1_SPI_CLK: 1R15.1 1U3.6(SCLK)
S1_1_SPI_CS: 1R10.2 1U3.1(CS#)
S1_1_SPI_DATA0: 1R17.1 1U3.5(SI/SIO0)
S1_1_SPI_DATA1: 1R11.2 1U3.2(SO/SIO1)
S1_1_SPI_DATA2: 1R14.2 1R16.2 1R18.2 1U3.3(WP#/SIO2)
S1_1_SPI_DATA3: 1R12.1 1R13.1 1U3.7(RST#/SIO3)
S1_1_VDD09: 1BD1.1 1BD2.1 1BD37.1 1C60.1 1R48.2 1R76.1 1R77.1 1R78.1 1R79.1 1ST13.2
S1_1_VDD18_A: 1K26.2 1K26.5 1R50.1 S1_1V3.1(TP)
S1_1_VDD18_D: 1C113.2 1R53.2 1R81.1 1R82.1 1R83.1 1ST15.1
S1_2_AOUT_LN: 1K12.4 1R68.2
S1_2_AOUT_LP: 1K12.5 1R69.2
S1_2_AOUT_RN: 1K15.4 1R64.2
S1_2_AOUT_RP: 1K15.5 1R65.2
S1_2_VDD18_A: 1BD16.1 1BD17.1 1BD19.1 1BD20.1 1C89.1 1R50.2
S1_ATX_VD0V9: 1C65.1 1C66.1 1K21.6 1ST3.2 ; also on sheet 27
S1_ATX_VD1V8: 1J7.1 1J8.1 1J9.1 ; also on sheet 27
S1_ATX_VD33: 1BD33.1 1C131.1 1C132.1 1C133.1 1C134.1 1C135.1 1J6.2 ; also on sheet 27
S1_AVCC_DRV: 1C75.1 1C110.1 1R55.2 1ST14.1 SITE1.53(AVCC_DRV)
S1_CHIP_EN_1: 1R34.2 1SW5.1
S1_DPS_F001: 1C120.1 1C121.1 1J9.2 1K29.6 1ST11.2
S1_DPS_F002: 1C92.1 1C93.1 1C94.1 1C95.1 1J8.2 1K26.6 1ST8.2
S1_DPS_F004: 1C140.1 1C141.1 1J7.2 1K20.6 1ST12.2
S1_DPS_F006: 1C68.1 1C69.1 1C70.1 1C71.1 1C72.1 1K23.3 1K23.6 1ST4.2 S1_VD33_ALL1.1(TP)
S1_DPS_GS001: 1ST19.1
S1_DPS_GS002: 1ST18.1
S1_DPS_GS003-1: 1ST16.1
S1_DPS_GS004: 1ST17.1
S1_DPS_GS006: 1ST5.1
S1_DPS_S001: 1ST11.1
S1_DPS_S002: 1ST8.1
S1_DPS_S003-1: 1ST3.1
S1_DPS_S004: 1ST12.1
S1_DPS_S006: 1ST4.1
S1_HSDM: 1K5.8 SITE1.79(HSDM)
S1_HSDP: 1K5.2 SITE1.78(HSDP)
S1_LPC_001: 1K36.7
S1_LPC_002: 1K36.2
S1_LPC_003: 1K11.2
S1_LPC_005: 1K14.2
S1_LPC_006: 1K18.4
S1_LPC_007: 1K1.4
S1_LPC_008: 1K35.2
S1_LPC_010: 1K34.7
S1_LPC_013+: 1K5.3 1K7.2
S1_LPC_013-: 1K5.7 1K7.8
S1_LPC_016: 1K2.5
S1_LPC_017: 1K35.7
S1_LPC_019: 1K12.2
S1_LPC_021: 1K1.5
S1_LPC_022: 1K15.2
S1_LPC_023: 1K3.4
S1_LPC_024: 1J4.2 1R35.1 SITE1.69(UART2_TXD/TEST_MODE_SEL/DMIC0_CLK/GPIOF_1/PB[22])
S1_LPC_025: 1J4.1 1R34.1 SITE1.71(CHIP_EN)
S1_LPC_026: 1K2.4
S1_LPC_027: 1K10.2
S1_LPC_028: 1K10.7
S1_LPC_029: 1K13.7
S1_LPC_030: 1K16.2
S1_LPC_032: 1K15.7
S1_LPC_033: 1K14.7
S1_LPC_034: 1K18.5
S1_LPC_035: 1K12.7
S1_LPC_036: 1K34.2
S1_LPC_038: 1K13.2
S1_LPC_039: 1K3.5
S1_LPC_040: 1K11.7
S1_LPC_041: 1J4.3 1R36.1 SITE1.68(UART2_RXD/BOOT_SEL/DMIC0_DATA/GPIOF_0/PB[21])
S1_LPC_042: 1C18.2 SITE1.50(MIC_BIAS2/GPIOC_13/PA[31])
S1_LPC_044: 1J4.5 1R39.1 SITE1.58(I2S3_DOUT1/DMIC_DATA2/ICFG1/GPIOD_4/PB[11])
S1_LPC_045: 1K39.3
S1_LPC_046: SITE1.67(I2S2_DIN3/I2S3_DOUT3/SPK_CLK/SPI0_CS/GPIOE_6/PB[20])
S1_LPC_047: 1J4.7 1R41.1 SITE1.18(GPIOB_7/PA[16]/ICFG3/SPI0_CS/UART0_RTS/HP_I2C2_SCL/ANT_SEL_N)
S1_LPC_048: 1K6.4
S1_LPC_049: SITE1.8(GPIOA_5/PA[5]/TOUCH5/ADC5/UART1_TXD/SPI1_MOSI/PWM4)
S1_LPC_050: SITE1.7(GPIOA_4/PA[4]/TOUCH4/ADC4/UART1_RXD/SPI1_MISO/PWM3/HP_I2C1_SCL)
S1_LPC_051: 1C17.2 SITE1.49(MIC_BIAS1/GPIOC_12/PA[30])
S1_LPC_052: 1C21.1 SITE1.48(AVCC)
S1_LPC_053: 1J4.4 1R37.1 SITE1.57(I2S3_DOUT0/DMIC_DATA1/ICFG0/BT_LOG/GPIOD_3/PB[10])
S1_LPC_054: 1K6.5
S1_LPC_055: SITE1.10(VBAT_MEAS)
S1_LPC_057: 1K9.4
S1_LPC_058: 1J4.6 1R40.1 SITE1.17(GPIOB_6/PA[15]/ICFG2/SPI0_CLK/UART0_CTS/HP_I2C2_SDA/ANT_SEL_P)
S1_LPC_059: 1K39.6
S1_LPC_060: SITE1.66(I2S2_DIN2/I2S3_DOUT2/SPK_DATA/SPI0_CK/GPIOE_5/PB[19])
S1_LPC_A_015: 1K8.4
S1_LPC_A_020: 1K8.5
S1_LPC_B_031: 1K4.4
S1_LPC_B_037: 1K4.5
S1_LX_AUD: 1K20.3 SITE1.100(LX_AUD)
S1_LX_AUD_CH_1: 1K20.4 ; also on sheet 4
S1_LX_AUD_CH_2: 1ST14.2 ; also on sheet 4
S1_LX_DCORE: 1K21.3 SITE1.3(LX_DCORE)
S1_LX_DCORE_CH: 1K21.4 ; also on sheet 4
S1_LX_MEM: 1K29.3 SITE1.75(LX_MEM)
S1_LX_MEM_CH_1: 1K29.4 ; also on sheet 4
S1_LX_MEM_CH_2: 1ST15.2 ; also on sheet 4
S1_MIPITX_CKN: 1K36.6 SITE1.82(MIPITX_CKN)
S1_MIPITX_CKP: 1K36.3 SITE1.83(MIPITX_CKP)
S1_MIPITX_DATAN_0: 1K34.6 SITE1.85(MIPITX_DATAN_0)
S1_MIPITX_DATAN_1: 1K35.6 SITE1.80(MIPITX_DATAN_1)
S1_MIPITX_DATAP_0: 1K34.3 SITE1.86(MIPITX_DATAP_0)
S1_MIPITX_DATAP_1: 1K35.3 SITE1.81(MIPITX_DATAP_1)
S1_PA2: 1K18.3 SITE1.5(GPIOA_2/PA[2]/TOUCH2/ADC2/UART0_RXD/SPI1_CS)
S1_PA3: 1K18.6 SITE1.6(GPIOA_3/PA[3]/TOUCH3/ADC3/UART0_TXD/SPI1_CLK/LEDC/HP_I2C1_SDA)
S1_PA9_CH: 1K39.2 SITE1.12(GPIOB_0/PA[9])
S1_PA10_CH: 1K39.7 SITE1.13(GPIOB_1/PA[10])
S1_PA13: 1K6.3 SITE1.15(GPIOB_4/PA[13]/SWD_DATA/SPI0_MOSI/UART0_RXD/HP_I2C1_SDA)
S1_PA13_UART_RX: 1K6.2 1R27.1
S1_PA13_UART_RX_1: 1J2.3 1R27.2
S1_PA14: 1K6.6 SITE1.16(GPIOB_5/PA[14]/SWD_CLK/SPI0_MISO/UART0_TXD/HP_I2C1_SCL)
S1_PA14_UART_TX: 1K6.7 1R28.1
S1_PA14_UART_TX_1: 1J2.4 1R28.2
S1_PA15_1: 1R40.2 1SW5.6
S1_PA16_1: 1R41.2 1SW5.7
S1_PA20: 1K15.6 SITE1.45(MIC1_P/GPIOC_2/PA[20])
S1_PA21: 1K15.3 SITE1.46(MIC1_N/GPIOC_3/PA[21])
S1_PA22: 1K11.6 SITE1.43(MIC2_P/GPIOC_4/PA[22])
S1_PA23: 1K11.3 SITE1.44(MIC2_N/GPIOC_5/PA[23])
S1_PA24: 1K12.6 SITE1.41(MIC3_P/I2C_SDA/GPIOC_6/PA[24])
S1_PA25: 1K12.3 SITE1.42(MIC3_N/I2C_SCL/GPIOC_7/PA[25])
S1_PA28: 1K13.6 SITE1.39(MIC5_P/ANT_SEL_P/GPIOC_10/PA[28])
S1_PA29: 1K13.3 SITE1.40(MIC5_N/ANT_SEL_N/GPIOC_11/PA[29])
S1_PB3: 1K10.6 SITE1.52(AOUT_LP/GPIOC_17/PB[3])
S1_PB3_AOUT_LP_2: 1K13.5 1R70.2
S1_PB4: 1K10.3 SITE1.51(AOUT_LN/GPIOC_18/PB[4])
S1_PB4_AOUT_LN_2: 1K13.4 1R67.2
S1_PB5: 1K14.6 SITE1.54(AOUT_RP/GPIOC_19/PB[5])
S1_PB5_AOUT_RP_2: 1K11.5 1R66.2
S1_PB6: 1K14.3 SITE1.55(AOUT_RN/GPIOC_20/PB[6])
S1_PB6_AOUT_RN_2: 1K11.4 1R63.2
S1_PB10_1: 1R37.2 1SW5.4
S1_PB11_1: 1R39.2 1SW5.5
S1_PB21_1: 1R36.2 1SW5.3
S1_PB22_1: 1R35.2 1SW5.2
S1_PB23: 1C144.2 1K4.3 1R57.1 SITE1.72(UART_LOG_RXD/OTP_BYPASS/GPIOF_2/PB[23])
S1_PB23_1: 1R57.2 1SW6.1
S1_PB23_SICK: 1K4.2 1R20.1
S1_PB23_SICK_1: 1J1.3 1R20.2
S1_PB24: 1C143.2 1K4.6 1R58.1 SITE1.73(UART_LOG_TXD/UART_DOWNLOAD/GPIOF_3/PB[24])
S1_PB24_1: 1R58.2 1SW6.2
S1_PB24_SIDD: 1K4.7 1R21.1
S1_PB24_SIDD_1: 1J1.4 1R21.2
S1_PB25: 1K8.3 1R59.1 SITE1.96(SPI0_CLK/SWD_CLK/SD_D2/ICFG2/GPIOG_0/PB[25])
S1_PB25_1: 1R59.2 1SW6.3
S1_PB25_I2C_SCL: 1K8.2 1R31.1
S1_PB25_I2C_SCL_1: 1J3.3 1R31.2
S1_PB26: 1K8.6 1R60.1 SITE1.97(SPI0_CS/SWD_DATA/SD_D3/ICFG3/GPIOG_1/PB[26])
S1_PB26_1: 1R60.2 1SW6.4
S1_PB26_I2C_SDA: 1K8.7 1R32.1
S1_PB26_I2C_SDA_1: 1J3.4 1R32.2
S1_RF_A: 1C13.1 1C14.1 1C15.1 1D3.1(CATHODE_D1) 1SMP3.1
S1_RF_G: 1C6.1 1C7.1 1C8.1 1D2.1(CATHODE_D1) 1SMP2.1
S1_RFIN_A: 1C16.2 1R9.1 SITE1.29(RFIN_A/GND_(<750um))
S1_RFIN_G: 1C9.2 1R5.1 SITE1.31(RFIN_G/GND)
S1_RFIO_A: 1C11.2 1R6.1 SITE1.28(RFIO_A__(<750um))
S1_RFIO_BT: 1C1.2 1R1.1 SITE1.37(RFIO_BT)
S1_RFIO_G: 1C4.2 1R2.1 SITE1.32(RFIO_G)
S1_RREF_MEM: 1K9.3 1R43.1 SITE1.60(RREF_MEM)
S1_SPI_CLK: 1K1.7 1R15.2
S1_SPI_CLK/PB28: 1K1.6 SITE1.90(SPI_FLASH_CLK/SD_CLK/GPIOG_3/PB[28])
S1_SPI_CS: 1K3.2 1R10.1
S1_SPI_CS/PC0: 1K3.3 SITE1.95(SPI_FLASH_CS/UART1_CTS/SD_CD/GPIOG_7/PC[0])
S1_SPI_D0/PB29: 1K1.3 SITE1.91(SPI_FLASH_DATA0/UART1_RXD/SD_D0/GPIOG_4/PB[29])
S1_SPI_D1/PB31: 1K3.6 SITE1.94(SPI_FLASH_DATA1/UART1_RTS/SD_WP/GPIOG_6/PB[31])
S1_SPI_D2/PB30: 1K2.6 SITE1.92(SPI_FLASH_DATA2/UART1_TXD/SD_D1/GPIOG_5/PB[30])
S1_SPI_D3/PB27: 1K2.3 SITE1.89(SPI_FLASH_DATA3/SD_CMD/GPIOG_2/PB[27])
S1_SPI_DATA0: 1K1.2 1R17.2
S1_SPI_DATA1: 1K3.7 1R11.1
S1_SPI_DATA2: 1K2.7 1R16.1
S1_SPI_DATA3: 1K2.2 1R13.2
S1_U1_VC1: 1K39.5 1U1.4(VCTL)
S1_U2_VC1: 1K39.4 1U2.4(VCTL)
S1_VA09_MIPI: 1BD37.2 1C152.1 SITE1.84(VA09_MIPI/VA09_CK/VA09_DA)
S1_VA09_PLL: 1BD1.2 1C44.1 SITE1.11(VA09_PLL/VD09_CORE0)
S1_VA09_USB: 1BD2.2 1C45.1 SITE1.77(VA09_USB)
S1_VA13_AFE: 1BD20.2 1C88.1 SITE1.19(VA13_AFE)
S1_VA13_SYN: 1BD16.2 1C78.1 SITE1.23(VR13_SYN)
S1_VA33_SYN: 1BD13.2 1C64.1 SITE1.24(VR33_SYN)
S1_VA33_XTAL: 1BD5.2 1C48.1 SITE1.20(VA33_XTAL)
S1_VD09_CORE1: 1C47.1 1R76.2 SITE1.56(VD09_CORE1/VD09MEM0)
S1_VD09_CORE2: 1C49.1 1R77.2 SITE1.64(VD09_CORE2/VD09_MEM1)
S1_VD09_CORE3: 1C54.1 1R78.2 SITE1.87(VD09_CORE3/VA09_PLL)
S1_VD09_CORE4: 1C58.1 1R79.2 SITE1.98(VD09_CORE4)
S1_VD13_FE: 1BD19.2 1C85.1 SITE1.36(VD13_FE)
S1_VD13_RF: 1BD17.2 1C79.1 SITE1.25(VD13_RF)
S1_VD33_ALL: 1BD3.1 1BD5.1 1BD7.1 1BD9.1 1BD11.1 1BD12.1 1BD13.1 1BD15.1 1BD18.1 1BD21.1 1BD22.1 1BD23.1 1BD28.1 1BD29.1 1BD30.1 1BD31.1 1BD32.1 1BD36.1 1C67.1 1C96.1 1C101.1 1C122.1 1C129.1 1J5.1 1J6.1 1K23.2 1K23.7
S1_VD33_CM_BT: 1BD21.2 1C90.1 1C91.1 SITE1.35(VD33_CM_BT)
S1_VD33_EX_FLASH: 1BD32.2 1C22.1 1C127.1 1C128.1 1R12.2 1R14.1 1U3.8(VCC)
S1_VD33_IO0: 1BD7.2 1C52.1 SITE1.9(VA33_PLL/VD33_IO0)
S1_VD33_IO2: 1BD9.2 1C56.1 SITE1.59(VD33_IO2/VD33_MEM)
S1_VD33_IO3: 1BD11.2 1C59.1 SITE1.70(VD33_IO3/VDD_IO4/VA33_USB)
S1_VD33_IO6: 1BD12.2 1C61.1 SITE1.88(VD33_IO6/VDD33_IO5/VD33_FLASH)
S1_VD33_SPS_AUD: 1BD30.2 1C123.1 1C124.1 SITE1.1(VD33_SPS_AUD)
S1_VD33_SPS_DCORE: 1BD28.2 1C111.1 1C112.1 SITE1.2(VD33_SPS_DCORE)
S1_VD33_SPS_MEM: 1BD31.2 1C125.1 1C126.1 SITE1.76(VD33_SPS_MEM)
S1_VD33PA_A: 1BD23.2 1C99.1 1C100.1 SITE1.27(VD33PA_A)
S1_VD33PA_BT: 1BD18.2 1C83.1 1C84.1 SITE1.38(VD33PA_BT)
S1_VD33PA_G: 1BD15.2 1C76.1 1C77.1 SITE1.33(VD33PA_G)
S1_VD33PAD_A: 1BD22.2 1C97.1 1C98.1 SITE1.26(VD33PAD_A)
S1_VD33PAD_G: 1BD36.2 1C73.1 1C74.1 SITE1.34(VD33PAD_G)
S1_VD1833_IO1: 1BD3.2 1C46.1 SITE1.14(VD1833_IO1)
S1_VD1833_SDIO: 1BD29.2 1C118.1 1C119.1 SITE1.93(VD1833_SDIO)
S1_VD_MEM0: 1C102.1 1R81.2 SITE1.61(VD_MEM0)
S1_VD_MEM1: 1C105.1 1R82.2 SITE1.62(VD_MEM1)
S1_VD_MEM2: 1C107.1 1R83.2 SITE1.65(VD_MEM2)
S1_VDD09: 1K22.2 1K22.5 1K31.4 1R48.1 S1_VDD09.1(TP)
S1_VDD09_CH: 1ST13.1 ; also on sheet 4
S1_VDD18_A: 1K25.2 1K25.5 1K26.3 1K32.4 1R55.1 S1_VDD18_A.1(TP)
S1_VDD18_D: 1K28.2 1K28.5 1K30.4 1R29.2 1R53.1 S1_VDD18_D.1(TP)
S1_VDD33: 1BD33.2 1C130.1 1R19.1 1R24.1 1R30.1 1R38.2 1R61.2 1U1.6(VDD) 1U2.6(VDD)
S1_VDD33_J1: 1J1.1 1R19.2
S1_VDD33_J2: 1J2.1 1R24.2
S1_VDD33_J3: 1J3.1 1R30.2
S1_VREF_DRAM: 1C153.1 1K16.3 SITE1.63(VREF_DRAM/NC(PSRAM))
S1_XI: 1C25.2 1Y1.1 SITE1.22(XI)
S1_XO: 1C23.2 1Y1.3 SITE1.21(XO)
S0123_CBIT_001: 1K7.9(V-) ; also on sheet 2 8 11
S0123_CBIT_003: 1K6.8(V-) ; also on sheet 2 8 11
S0123_CBIT_004: 1K2.8(V-) ; also on sheet 2 8 11
S0123_CBIT_005: 1K3.8(V-) ; also on sheet 2 8 11
S0123_CBIT_006: 1K35.8(V-) ; also on sheet 2 3 9 12
S0123_CBIT_008: 1K30.8(V-) ; also on sheet 2 4 10 13
S0123_CBIT_009: 1K32.8(V-) ; also on sheet 2 4 10 13
S0123_CBIT_010: 1K31.8(V-) ; also on sheet 2 4 10 13
S0123_CBIT_011: 1K29.8(V-) ; also on sheet 2 4 10 13
S0123_CBIT_012: 1K28.8(V-) ; also on sheet 2 4 10 13
S0123_CBIT_013: 1K8.8(V-) ; also on sheet 2 8 11
S0123_CBIT_014: 1K26.8(V-) ; also on sheet 2 4 10 13
S0123_CBIT_015: 1K34.8(V-) ; also on sheet 2 3 9 12
S0123_CBIT_016: 1K16.8(V-) ; also on sheet 2 8 11
S0123_CBIT_017: 1K21.8(V-) ; also on sheet 2 4 10 13
S0123_CBIT_018: 1K18.8(V-) ; also on sheet 2 3 9 12
S0123_CBIT_019: 1K22.8(V-) ; also on sheet 2 4 10 13
S0123_CBIT_020: 1K9.8(V-) ; also on sheet 2 8 11
S0123_CBIT_022: 1K19.8(V-) ; also on sheet 2 3 9 12
S0123_CBIT_023: 1K23.8(V-) ; also on sheet 2 4 10 13
S0123_CBIT_024: 1K20.8(V-) ; also on sheet 2 4 10 13
S0123_CBIT_025: 1K13.8(V-) ; also on sheet 2 3 9 12
S0123_CBIT_026: 1K14.8(V-) ; also on sheet 2 3 9 12
S0123_CBIT_027: 1K15.8(V-) ; also on sheet 2 3 9 12
S0123_CBIT_028: 1K25.8(V-) ; also on sheet 2 4 10 13
S0123_CBIT_029: 1K10.8(V-) ; also on sheet 2 3 9 12
S0123_CBIT_030: 1K11.8(V-) ; also on sheet 2 3 9 12
S0123_CBIT_031: 1K12.8(V-) ; also on sheet 2 3 9 12
S0123_CBIT_032: 1K39.8(V-) ; also on sheet 2 8 11
S0123_CBIT_033: 1K1.8(V-) ; also on sheet 2 8 11
S0123_CBIT_035: 1K5.9(V-) ; also on sheet 2 8 11
S0123_CBIT_036: 1K36.8(V-) ; also on sheet 2 3 9 12
S0123_CBIT_037: 1K4.8(V-) ; also on sheet 2 8 11
VP12: 1K1.1(V+) 1K2.1(V+) 1K3.1(V+) 1K4.1(V+) 1K5.1(V+) 1K6.1(V+) 1K7.1(V+) 1K8.1(V+) 1K9.1(V+) 1K10.1(V+) 1K11.1(V+) 1K12.1(V+) 1K13.1(V+) 1K14.1(V+) 1K15.1(V+) 1K16.1(V+) 1K18.1(V+) 1K19.1(V+) 1K20.1(V+) 1K21.1(V+) 1K22.1(V+) 1K23.1(V+) 1K25.1(V+) 1K26.1(V+) 1K28.1(V+) 1K29.1(V+) 1K30.1(V+) 1K31.1(V+) 1K32.1(V+) 1K34.1(V+) 1K35.1(V+) 1K36.1(V+) 1K39.1(V+) ; also on sheet 2 3 4 8 9 10 11 12 13 14 15 16 17 18 19 20 21 22 23 24 25 26 27 29 38
N27439655: 1C10.1 1R5.2 1U1.3(RF2)
N27439661: 1C7.2 1U1.5(ANT)
N27439664: 1R4.1 1U1.1(RF1)
N27439715: 1C6.2 1R3.2
N27439724: 1C19.1 1R9.2 1U2.1(RF1)
N27439731: 1C14.2 1U2.5(ANT)
N27439738: 1C12.1 1R6.2 1R7.1 1R8.2
N27439740: 1C13.2 1R7.2
N27439759: 1BD27.2 1C24.1 1K16.4
N27439769: 1K5.6 1R22.1
N27439771: 1K5.4 1R25.1
N27439774: 1R8.1 1U2.3(RF2)
N27439780: 1C5.1 1R2.2 1R3.1 1R4.2
N27439808: 1C2.1 1C3.1 1R1.2
N27439813: 1C2.2 1D1.1(CATHODE_D1) 1SMP1.1
N27439931: 1K7.6 1R23.1
N27439932: 1K7.4 1R26.1
N27439937: 1BD27.1 1R29.1 1R33.2
N27440064: 1C20.1 SITE1.47(VREF_AUDIO)
N27443663: 1K18.2 1K19.3
N27443664: 1K18.7 1K19.6
N27443667: 1C39.1 1K19.4
N27443668: 1C38.2 1K19.2
N27443671: 1C41.1 1K19.5
N27443672: 1C40.2 1K19.7
N27443703: 1R47.2 1R74.2
N27443785: 1R45.2 1R75.2
N27443801: 1C145.2 1K34.4
N27443802: 1C146.2 1K34.5
N27443809: 1C147.2 1K35.4
N27443810: 1C148.2 1K35.5
N27443813: 1C149.2 1K36.4
N27443814: 1C150.2 1K36.5
N27444901: 1K21.2 1L1.1
N27444931: 1K29.2 1L3.1
N27444932: 1C106.1 1C108.1 1C109.1 1K28.3 1L3.2
N27444943: 1K28.4 1R54.1
N27444947: 1C116.1 1C117.1 1K28.6 1K29.5
N27444970: 1C53.1 1C55.1 1C57.1 1K22.3 1L1.2
N27444982: 1K22.4 1R49.1
N27444986: 1C62.1 1C63.1 1K21.5 1K22.6
N27445101: 1K20.2 1L4.1
N27445102: 1C136.1 1C137.1 1C138.1 1K25.3 1L4.2
N27445113: 1K25.4 1R51.1
N27445115: 1C139.1 1C142.1 1K20.5 1K25.6
N27445221: 1K30.3 1R71.1
N27445223: 1K31.3 1R72.1
N27445225: 1K32.3 1R73.1
N27678036: 1R62.1 1SW6.5
N27678040: 1R61.1 1SW6.6
N27678099: 1R42.1 1SW5.9
N27678103: 1R38.1 1SW5.10

Not connected (* = marked no-connect by the designer): 1K7 3* 7*; 1K9 2* 5* 6* 7*; 1K16 5* 6* 7*; 1K20 7*; 1K21 7*; 1K22 7*; 1K23 4* 5*; 1K25 7*; 1K26 4* 7*; 1K28 7*; 1K29 7*; 1K30 2* 5* 6* 7*; 1K31 2* 5* 6* 7*; 1K32 2* 5* 6* 7*; 1SW5 8*; SITE1 GH1* GH2* GH3* GH4* NUT1* NUT2* NUT3* NUT4*

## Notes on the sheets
sheet 5
- WIFI/BT_RF
- place by Z-shape
- R3 and R4 Share PAD,
  Default R3
- C6 and C7 Share PAD,
  Default C6
- place by Z-shape
- place by Z-shape
- R7 and R8 Share PAD,
  Default R7
- C13 and C14 Share PAD,
  Default C13
- place by Z-shape
- place by Z-shape
- GND Shielding
- FLASH
- RF SW Channel  and PA9.10 share one Channel
- GND Shielding
- Mark On Board
- Debug
- GND Shielding
- 1.S0_VDD33
- 2.GND
- 3.S0_SICK
- DSSC
- 4.S0_SIDD
- SIC
- USB
- GND Shielding
- Mark On Board
- Debug
- 1.S0_VDD33
- 2.GND
- 3.S0_UART_RX
- 4.S0_UART_TX
- UART
- DIFF 90ohm
- DIFF 90ohm
- Mark On Board
- Debug
- XTAL
- VREF_DRAM
- 1.S0_VDD33
- GND Shielding
- 2.GND
- Close To DUT
- 3.S0_I2C_SCL
- DSSC
- 4.S0_I2C_SDA
- BT_I2C
- GND Shielding
- Mark On Board
- 1.S0_CHIP_EN
- 2.S0_PB22_TEST_MODE_SEL
- 3.S0_PB21_BOOT_SEL_FLASH
- 4.S0_PB10/ICFG0
- 5.S0_PB11/ICFG1
- 6.S0_PA15/ICFG2
- 7.S0_PA16/ICFG3
- 8.NC
- RREF
- Close to Relay
- Close To DUT
sheet 6
- AUDIO ADC Test
- MIPI Test
- GND Shielding
- GND Shielding
- CAP TOUCH Test
- GND Shielding
sheet 7
- CLOSE TO DUT
- POWER_VD09
- POWER_VD1833
- CLOSE TO DUT
- 110mA
- 5mA
- 33mA
- C48 TOP
- 20mA
- 102mA
- 35mA
- 105mA
- 35mA
- 112mA
- 25mA
- 50mA
- Mark On Board : S0_VDD09
- C58 TOP
- 30mA
- 50mA
- 10mA
- C64 TOP
- 200mA
- CLOSE TO DUT
- 200mA
- POWER_VD18_AUD
- CLOSE TO DUT
- Mark On Board : S0_VDD18_A
- 200mA
- 100mA
- C75 TOP
- 50mA
- Mark On Board : S0_VDD33
- CLOSE TO DUT
- CLOSE TO DUT
- 45mA
- 60mA
- C78 TOP
- 80mA
- C79 TOP
- 45mA
- C97,C98 TOP
- 300mA
- 25mA
- C88 TOP
- C99,C100 TOP
- POWER_VD18_DDR
- CLOSE TO DUT
- CLOSE TO DUT
- 155mA
- 62mA
- C111,C112 TOP
- 62mA
- 30mA
- 62mA
- Mark On Board : S0_VDD18_D
- C107 TOP
- 107mA
- C123,C124 TOP
- 160mA
- C125,C126 TOP
- 50mA
- Calibration Loading SCH
